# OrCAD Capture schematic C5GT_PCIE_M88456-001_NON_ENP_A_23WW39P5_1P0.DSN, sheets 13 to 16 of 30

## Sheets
13 DDR3B - x64 SMC: size B
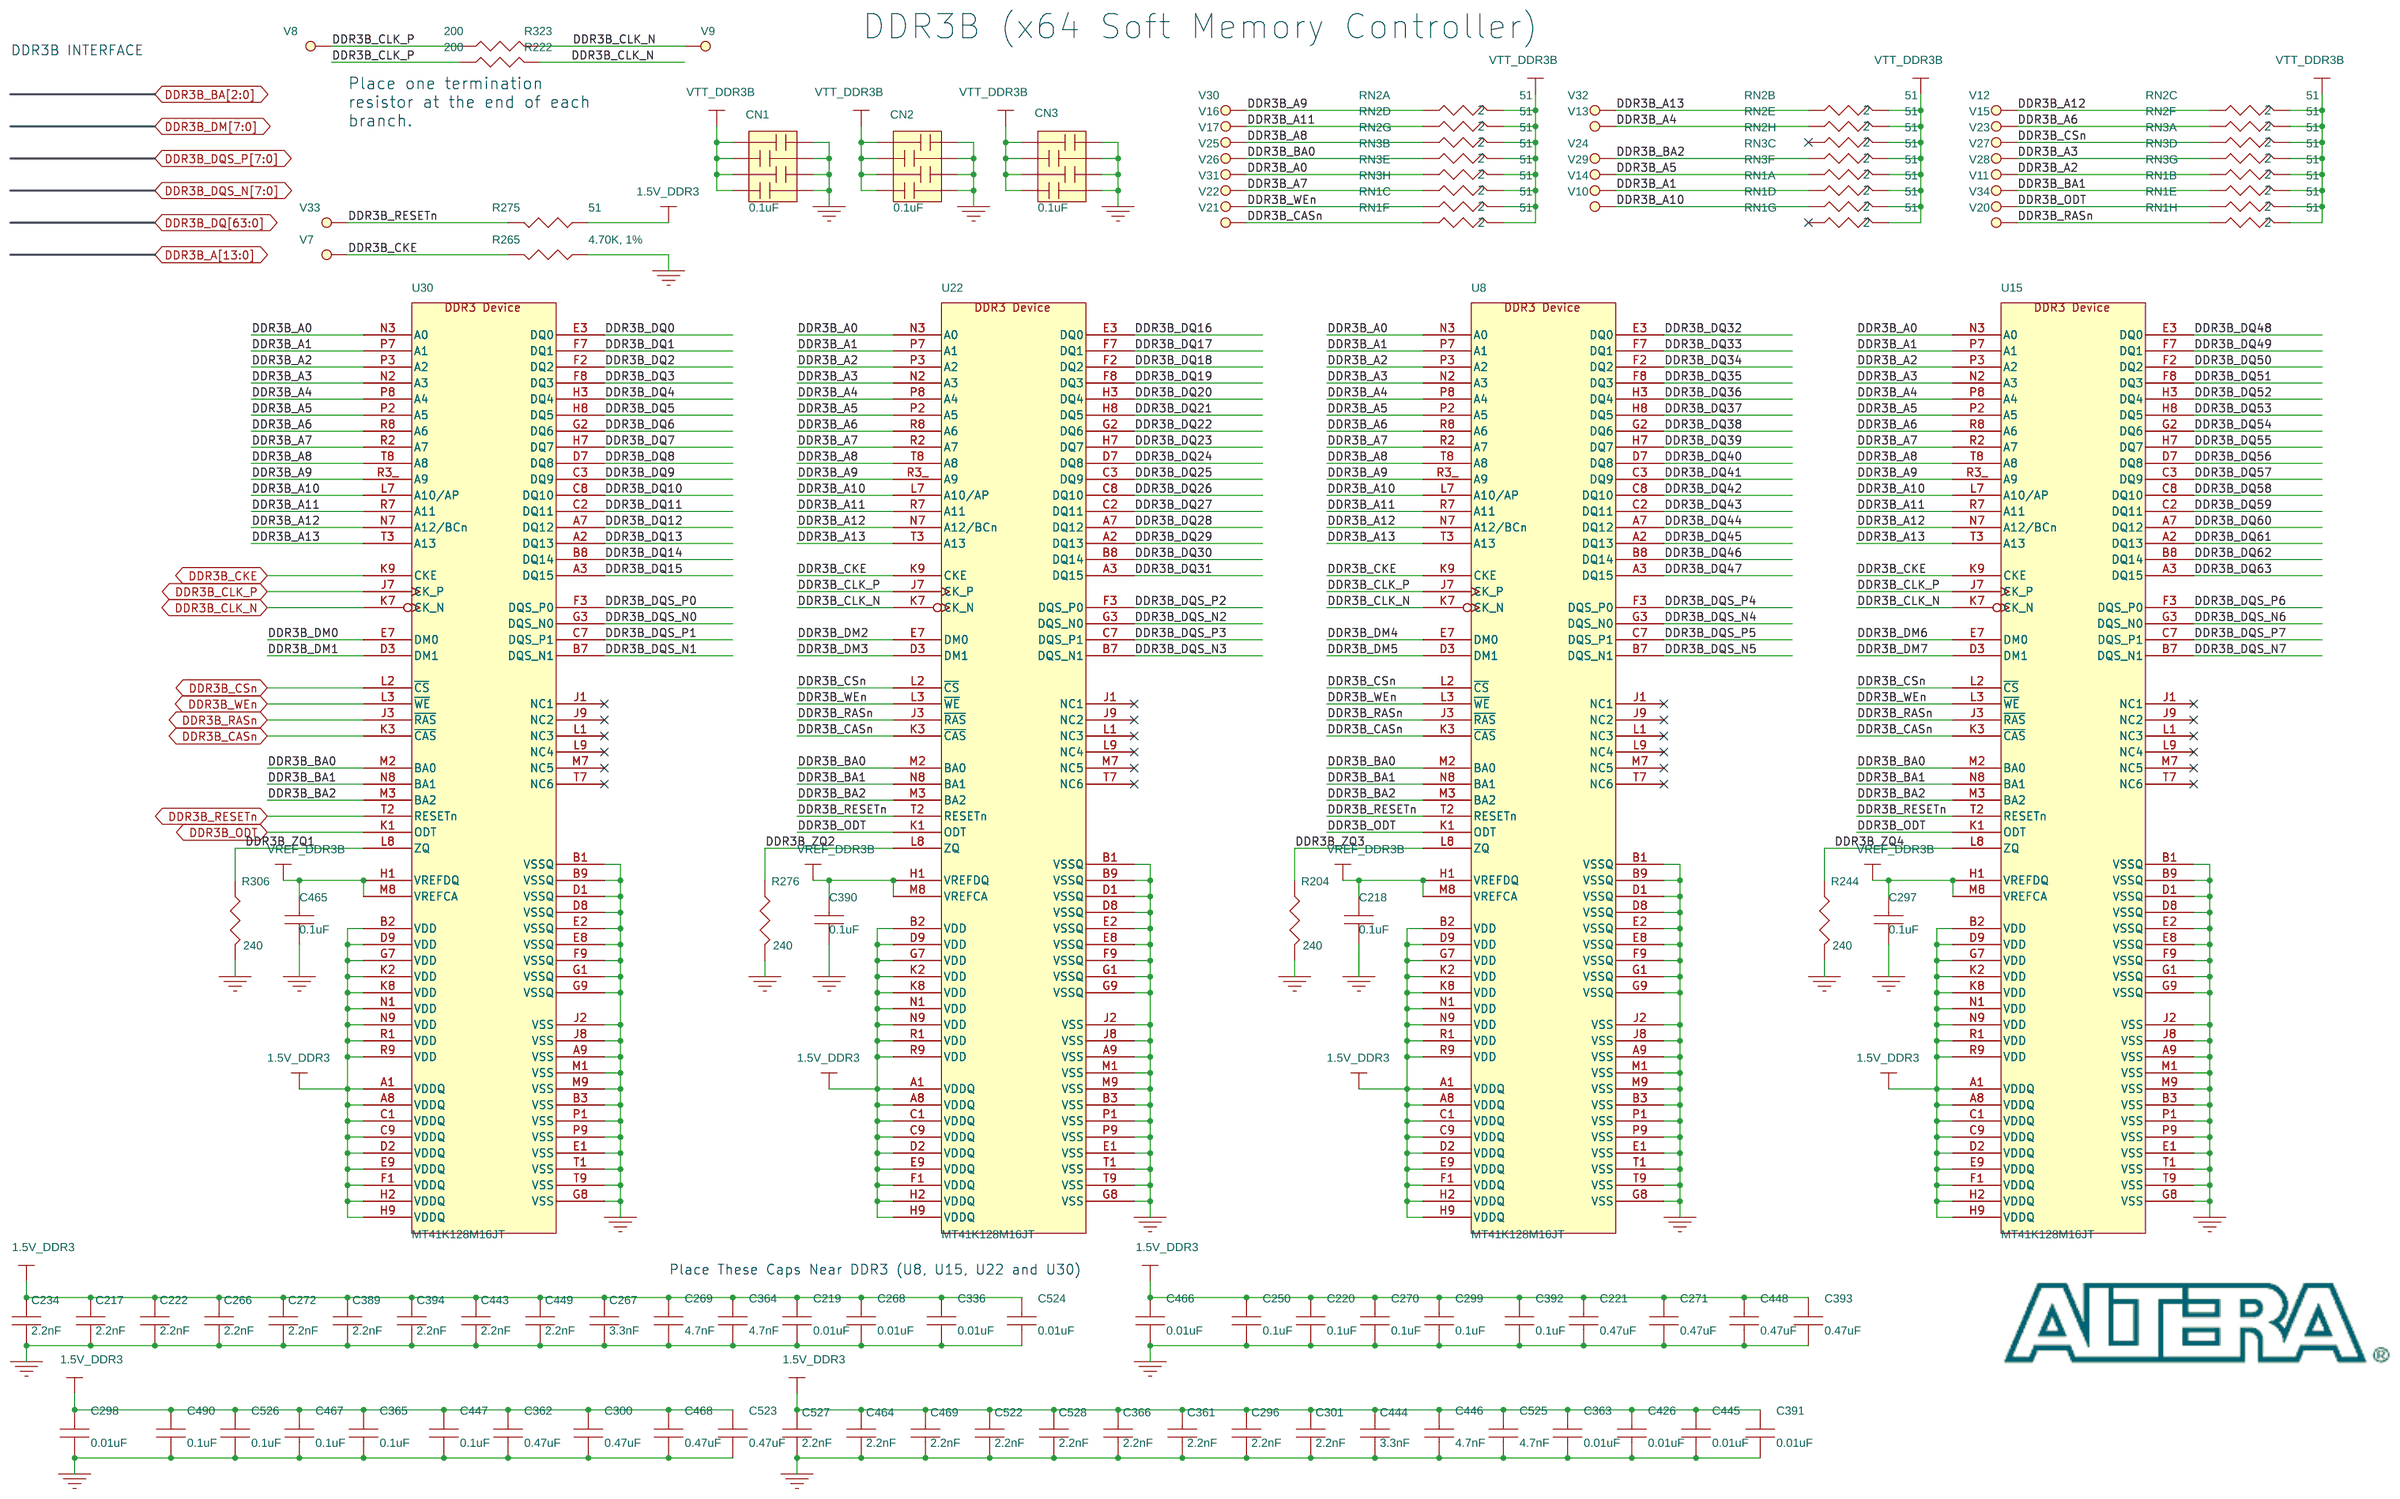
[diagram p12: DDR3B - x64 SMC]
14 Flash: size B
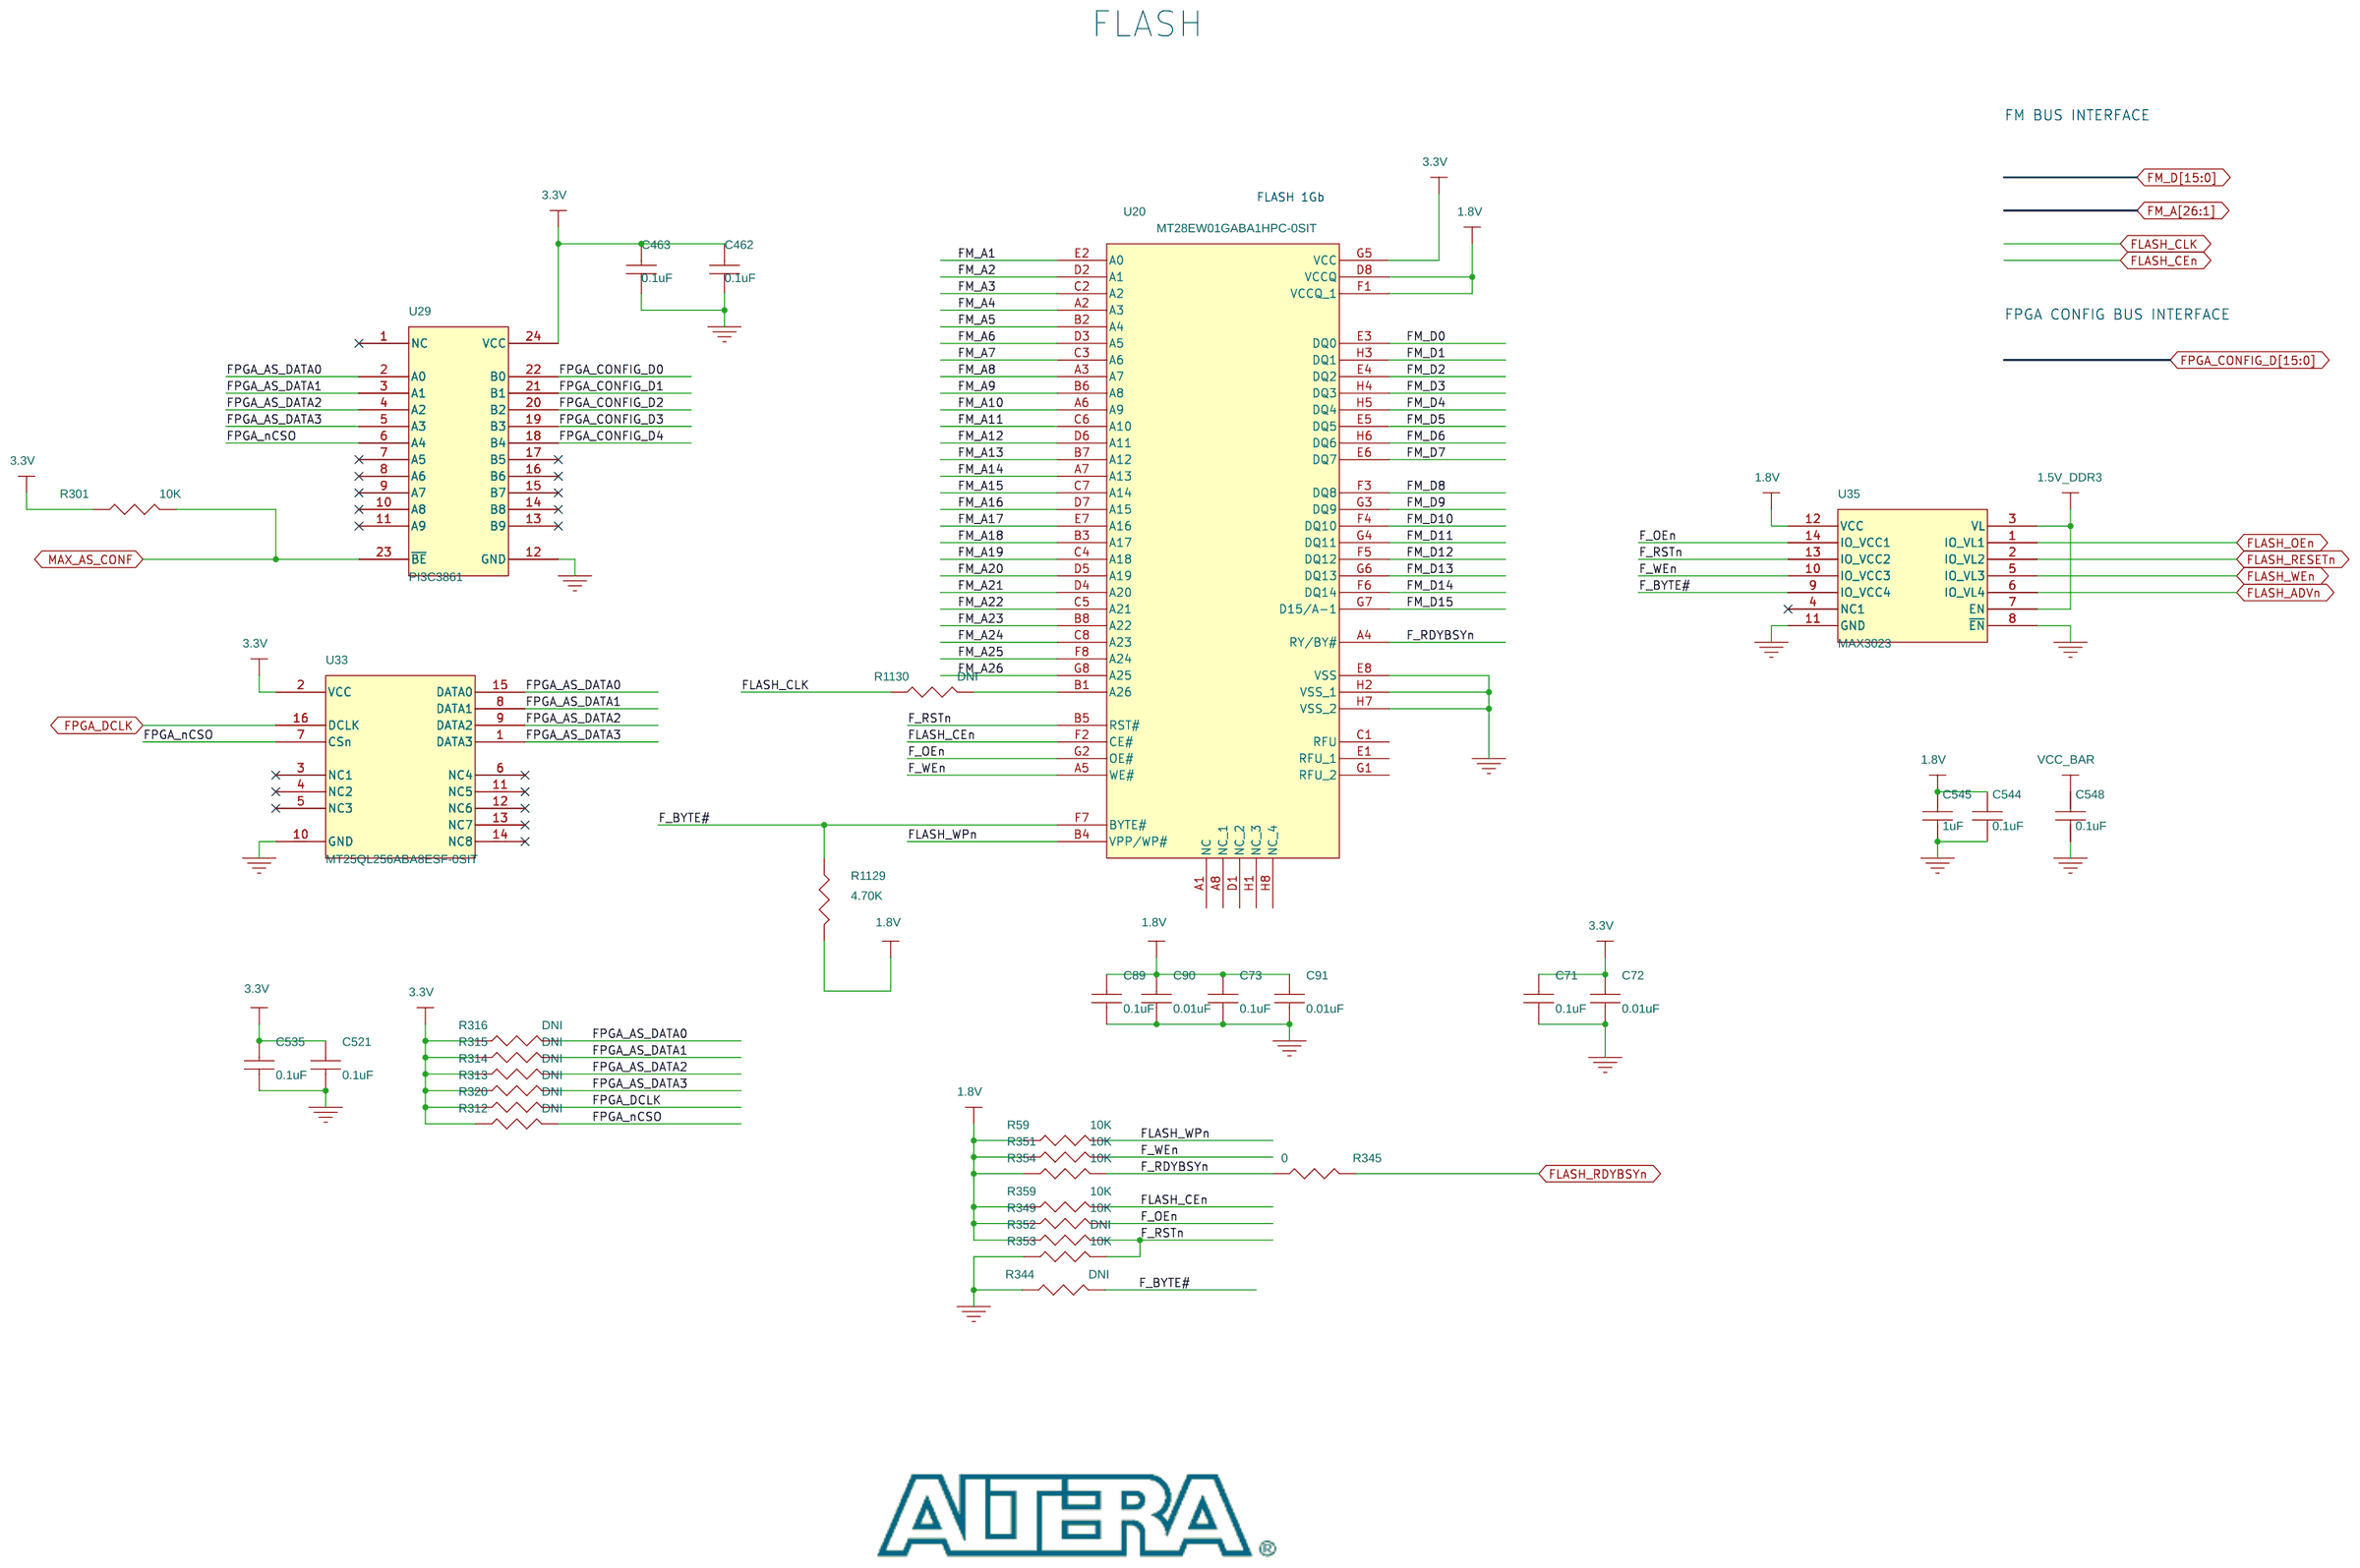
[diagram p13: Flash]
15 5M2210 System Controller: size B
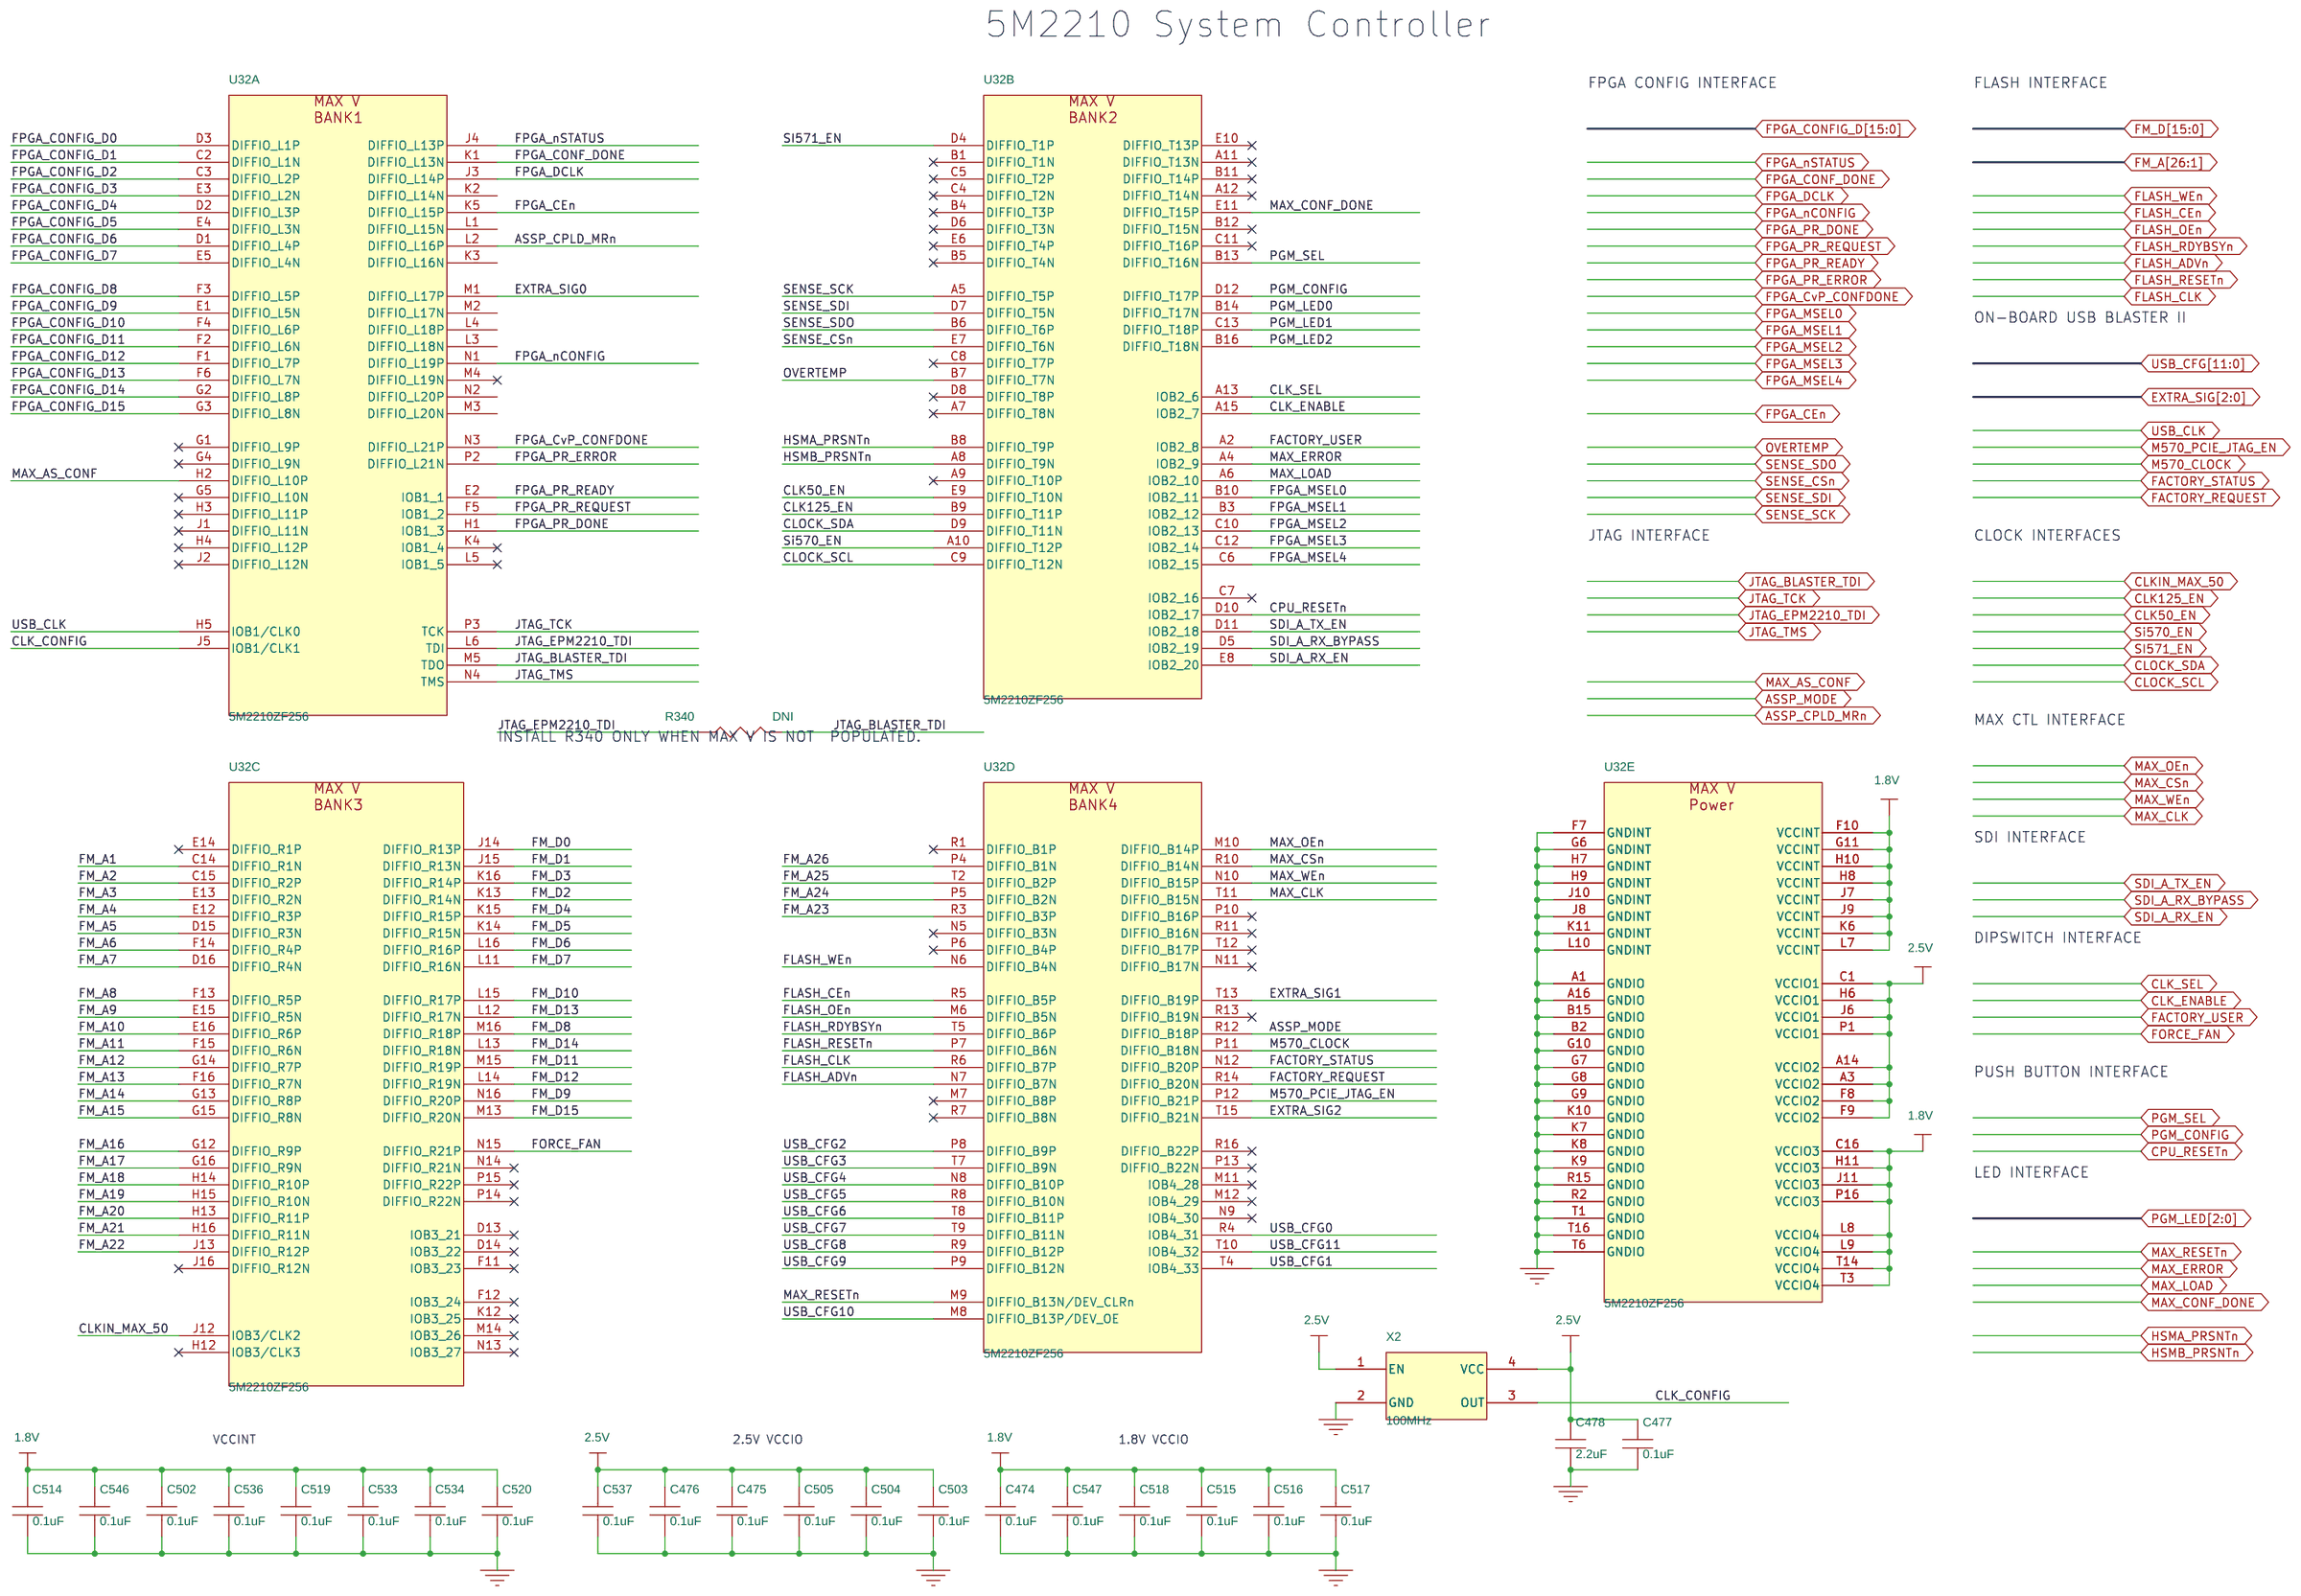
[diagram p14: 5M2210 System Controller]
16 SDI A Transmit/Receive: size B
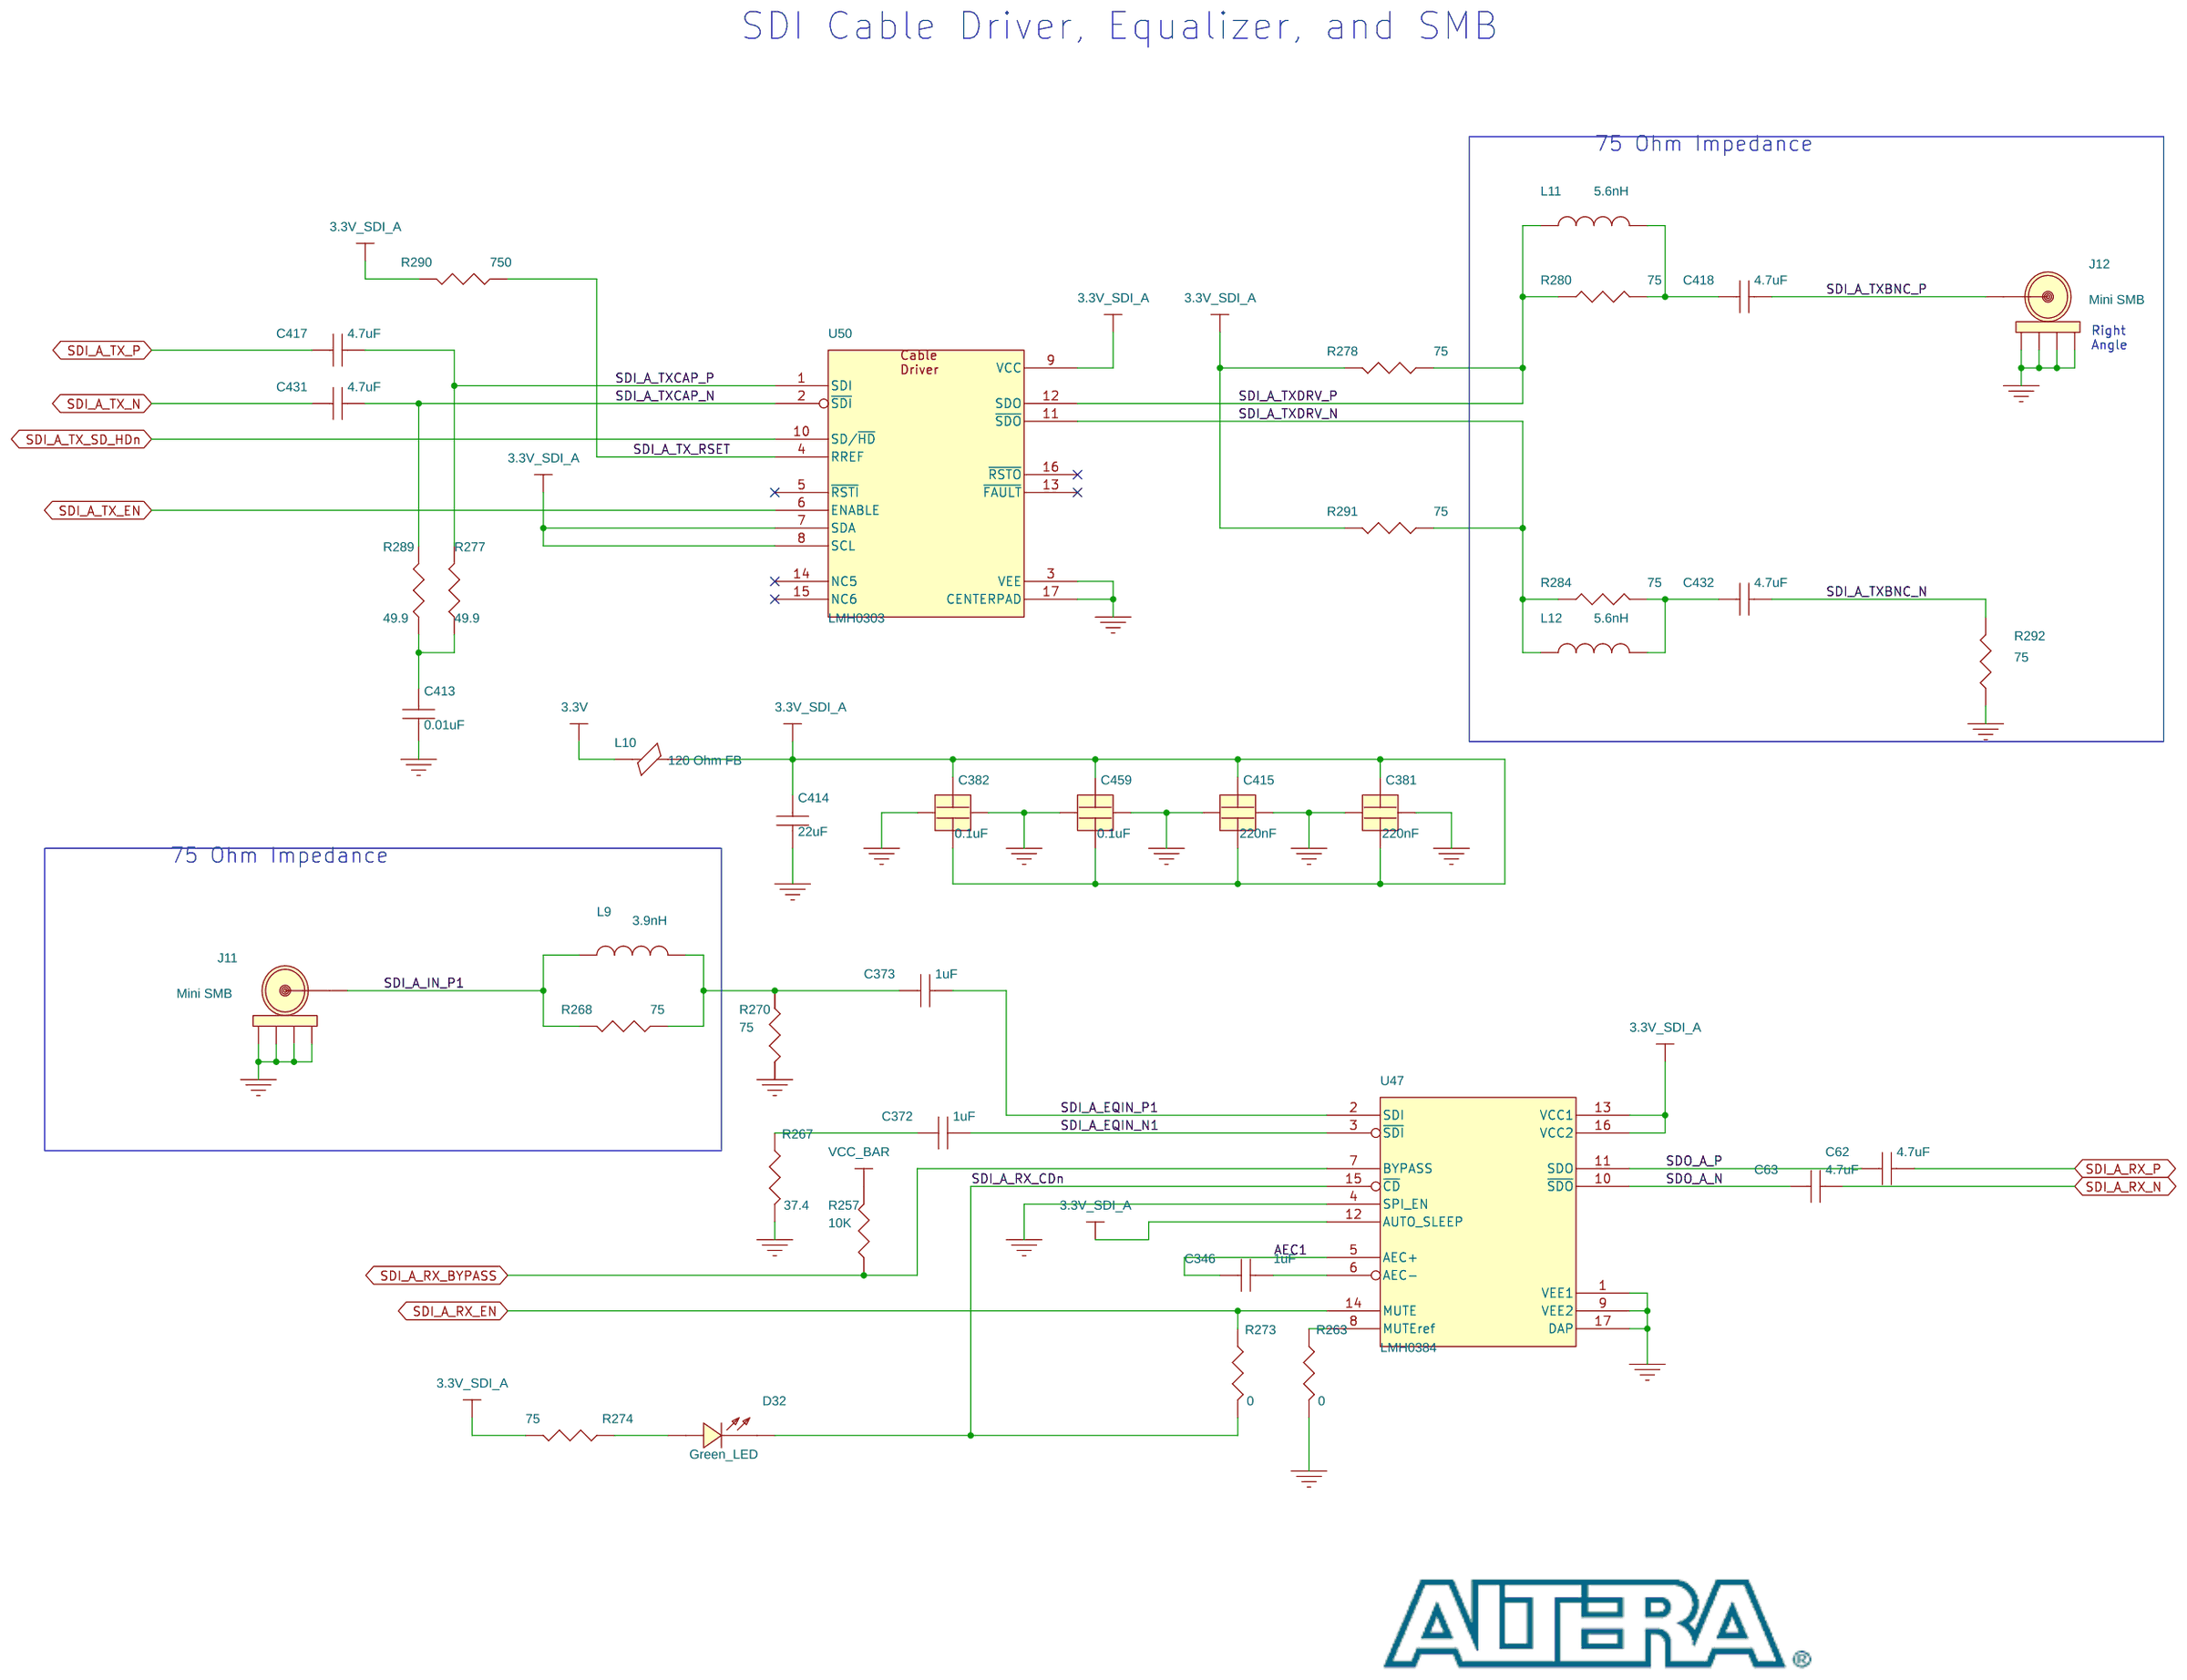
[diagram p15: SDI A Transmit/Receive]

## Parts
sheet 5M2210 System Controller
C474  0.1uF  [0402]
C475  0.1uF  [0402]
C476  0.1uF  [0402]
C477  0.1uF  [0402]
C478  2.2uF  [0603]
C502  0.1uF  [0402]
C503  0.1uF  [0402]
C504  0.1uF  [0402]
C505  0.1uF  [0402]
C514  0.1uF  [0402]
C515  0.1uF  [0402]
C516  0.1uF  [0402]
C517  0.1uF  [0402]
C518  0.1uF  [0402]
C519  0.1uF  [0402]
C520  0.1uF  [0402]
C533  0.1uF  [0402]
C534  0.1uF  [0402]
C536  0.1uF  [0402]
C537  0.1uF  [0402]
C546  0.1uF  [0402]
C547  0.1uF  [0402]
R340  DNI  [0402]
U32  5M2210ZF256  [F256]  (sections A,B,C,D,E)
X2  100MHz  [XTAL_XG-1000CB]
sheet DDR3B - x64 SMC
C217  2.2nF  [0402]
C218  0.1uF  [0402]
C219  0.01uF  [0402]
C220  0.1uF  [0402]
C221  0.47uF  [0402]
C222  2.2nF  [0402]
C234  2.2nF  [0402]
C250  0.1uF  [0402]
C266  2.2nF  [0402]
C267  3.3nF  [0402]
C268  0.01uF  [0402]
C269  4.7nF  [0402]
C270  0.1uF  [0402]
C271  0.47uF  [0402]
C272  2.2nF  [0402]
C296  2.2nF  [0402]
C297  0.1uF  [0402]
C298  0.01uF  [0402]
C299  0.1uF  [0402]
C300  0.47uF  [0402]
C301  2.2nF  [0402]
C336  0.01uF  [0402]
C361  2.2nF  [0402]
C362  0.47uF  [0402]
C363  0.01uF  [0402]
C364  4.7nF  [0402]
C365  0.1uF  [0402]
C366  2.2nF  [0402]
C389  2.2nF  [0402]
C390  0.1uF  [0402]
C391  0.01uF  [0402]
C392  0.1uF  [0402]
C393  0.47uF  [0402]
C394  2.2nF  [0402]
C426  0.01uF  [0402]
C443  2.2nF  [0402]
C444  3.3nF  [0402]
C445  0.01uF  [0402]
C446  4.7nF  [0402]
C447  0.1uF  [0402]
C448  0.47uF  [0402]
C449  2.2nF  [0402]
C464  2.2nF  [0402]
C465  0.1uF  [0402]
C466  0.01uF  [0402]
C467  0.1uF  [0402]
C468  0.47uF  [0402]
C469  2.2nF  [0402]
C490  0.1uF  [0402]
C522  2.2nF  [0402]
C523  0.47uF  [0402]
C524  0.01uF  [0402]
C525  4.7nF  [0402]
C526  0.1uF  [0402]
C527  2.2nF  [0402]
C528  2.2nF  [0402]
CN1  0.1uF  [CAP_PACK_4_1206]
CN2  0.1uF  [CAP_PACK_4_1206]
CN3  0.1uF  [CAP_PACK_4_1206]
R204  240  [0402]
R222  200  [0402]
R244  240  [0402]
R265  4.70K, 1%  [0402]
R275  51  [0402]
R276  240  [0402]
R306  240  [0402]
R323  200  [0402]
RN1  51  [RES_PACK_8]  (sections A,B,C,D,E,F,G,H)
RN2  51  [RES_PACK_8]  (sections A,B,C,D,E,F,G,H)
RN3  51  [RES_PACK_8]  (sections A,B,C,D,E,F,G,H)
U8  MT41K128M16JT  [Micron_ddr3_96_9x14]
U15  MT41K128M16JT  [Micron_ddr3_96_9x14]
U22  MT41K128M16JT  [Micron_ddr3_96_9x14]
U30  MT41K128M16JT  [Micron_ddr3_96_9x14]
V7  VIA_1  [STAR_VIA]
V8  VIA_1  [STAR_VIA]
V9  VIA_1  [STAR_VIA]
V10  VIA_1  [STAR_VIA]
V11  VIA_1  [STAR_VIA]
V12  VIA_1  [STAR_VIA]
V13  VIA_1  [STAR_VIA]
V14  VIA_1  [STAR_VIA]
V15  VIA_1  [STAR_VIA]
V16  VIA_1  [STAR_VIA]
V17  VIA_1  [STAR_VIA]
V20  VIA_1  [STAR_VIA]
V21  VIA_1  [STAR_VIA]
V22  VIA_1  [STAR_VIA]
V23  VIA_1  [STAR_VIA]
V24  VIA_1  [STAR_VIA]
V25  VIA_1  [STAR_VIA]
V26  VIA_1  [STAR_VIA]
V27  VIA_1  [STAR_VIA]
V28  VIA_1  [STAR_VIA]
V29  VIA_1  [STAR_VIA]
V30  VIA_1  [STAR_VIA]
V31  VIA_1  [STAR_VIA]
V32  VIA_1  [STAR_VIA]
V33  VIA_1  [STAR_VIA]
V34  VIA_1  [STAR_VIA]
sheet Flash
C71  0.1uF  [0402]
C72  0.01uF  [0402]
C73  0.1uF  [0402]
C89  0.1uF  [0402]
C90  0.01uF  [0402]
C91  0.01uF  [0402]
C462  0.1uF  [0402]
C463  0.1uF  [0402]
C521  0.1uF  [0402]
C535  0.1uF  [0402]
C544  0.1uF  [0402]
C545  1uF  [0402]
C548  0.1uF  [0402]
R59  10K  [0402]
R301  10K  [0402]
R312  DNI  [0402]
R313  DNI  [0402]
R314  DNI  [0402]
R315  DNI  [0402]
R316  DNI  [0402]
R320  DNI  [0402]
R344  DNI  [0402]
R345  0  [0402]
R349  10K  [0402]
R351  10K  [0402]
R352  DNI  [0402]
R353  10K  [0402]
R354  10K  [0402]
R359  10K  [0402]
R1129  4.70K  [0402]
R1130  DNI  [0402]
U20  MT28EW01GABA1HPC-0SIT  [hc_tk0_bga64]
U29  PI3C3861  [QSOP24P]
U33  MT25QL256ABA8ESF-0SIT  [so16_wide]
U35  MAX3023  [TSSOP14]
sheet SDI A Transmit/Receive
C62  4.7uF  [0402]
C63  4.7uF  [0402]
C346  1uF  [0603]
C372  1uF  [0603]
C373  1uF  [0603]
C381  220nF  [X2Y_1206]
C382  0.1uF  [X2Y_0603]
C413  0.01uF  [0402]
C414  22uF  [1210]
C415  220nF  [X2Y_1206]
C417  4.7uF  [0805]
C418  4.7uF  [0805]
C431  4.7uF  [0805]
C432  4.7uF  [0805]
C459  0.1uF  [X2Y_0603]
D32  Green_LED  [LUMEX_LED0805]
J11  Mini SMB  [SMB_RA_JACK_RECEP]
J12  Mini SMB  [SMB_RA_JACK_RECEP]
L9  3.9nH  [0402]
L10  120 Ohm FB  [0603]
L11  5.6nH  [0402]
L12  5.6nH  [0402]
R257  10K  [0402]
R263  0  [0402]
R267  37.4  [0402]
R268  75  [0402]
R270  75  [0402]
R273  0  [0402]
R274  75  [0402]
R277  49.9  [0402]
R278  75  [0402]
R280  75  [0402]
R284  75  [0402]
R289  49.9  [0402]
R290  750  [0603]
R291  75  [0402]
R292  75  [0402]
U47  LMH0384  [LLP16_EPAD]
U50  LMH0303  [LLP16_EPAD]

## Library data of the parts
C71 C73 C89 C220 C250 C270 C299 C365 C392 C447 C467 C474-C476 C490 C502-C505 C514-C521 C526 C533-C537 C544 C546-C548 = CAP: CAP - CERAMIC,  0.1UF 0402 25VDC Y5V; Dielectric: X5R; IPN: K13560-001; Item Num: P03-15057R; LIFECYCLE_PHASE: Active; Lead Free Status: Lead Free; Manufacturer: Murata; Manufacturer Part Num: GRM155F51E104ZA01D; Num Pins: 2; Part Class: CAPACITORS; Price: 0.07; RoHS Compliant: RoHS Compliant; Tolerance: +80%/-20%
C218 C390 C477 = CAP: CAP - CERAMIC,  0.1UF 0402 25VDC Y5V; AGILE_LINK: http://sj-agile9app/Agile/PLMServlet?action=OpenEmailObject&classid=10000&objid=213459527; IPN: K13560-001; Item Num: P03-15057R; LIFECYCLE_PHASE: Active; Lead Free Status: Lead Free; MFR_LIFECYCLE: Active; Manufacturer: Murata; Manufacturer Part Num: GRM155F51E104ZA01D; Num Pins: 2; PART_SUBCLASS: CAPACITORS; Part Class: CAPACITORS; RATED_VOLTAGE: 25V; RoHS Compliant: RoHS Compliant; TOLERANCE: +80%/-20%
C478 = CAP: CAP, CERAMIC, 2.2UF, 10%, 10VDC, X5R, 0603; AGILE_LINK: http://sj-agile9app/Agile/PLMServlet?action=OpenEmailObject&classid=10000&objid=256999866; IPN: M97320-001; Item Num: P03-15213R; LIFECYCLE_PHASE: Active; Lead Free Status: Lead Free; MFR_LIFECYCLE: Active; Manufacturer: Murata; Manufacturer Part Num: GRM188R61A225KE34x; Num Pins: 2; PART_SUBCLASS: CAPACITORS; RATED_VOLTAGE: 10V; RoHS Compliant: RoHS Compliant; Supplier Part Num: 490-1545-1-ND; TOLERANCE: +/-10%
R340 = RESISTOR: RES ZERO OHM 1/16W 5% 0402 SMD; Altera Part No.: P02-14020R; IPN: A93549-001; Item Num: P02-14020R; Lead Free Status: No; Manufacturer: Panasonic; Manufacturer Part Num: ERJ-2GE0R00X; Num Pins: 2; Part Class: RESISTORS; Price: 0; RoHS Compliant: Yes; Tolerance: 5%
U32 = 5M2210ZF256: IC - Max V CPLD, 2210 LEs, 256FBGA 1.8V VCCINT; IPN: 965739; Item Num: P01-17326R; LIFECYCLE_PHASE: Preliminary; Lead Free Status: Lead Free; MFR_LIFECYCLE: Active; Manufacturer: Altera Corporation; Manufacturer Part Num: 5M2210ZF256C4N; Num Pins: 256; PART_SUBCLASS: ICS; RoHS Compliant: RoHS Compliant
X2 = OSC_ALT_1: OSC - 100MHZ, +/-50PPM, 2.5V, CMOS CLOCK OSCILLATOR, SMD; AGILE_LINK: http://sj-agile9app/Agile/PLMServlet?action=OpenEmailObject&classid=10000&objid=261083657; IPN: E98724-001; Item Num: P13-26910R; LIFECYCLE_PHASE: Active; Lead Free Status: Lead Free; MFR_LIFECYCLE: Active; Manufacturer: ECS, Inc.; Manufacturer Part Num: ECS-3525-1000-B-TR; Num Pins: 4; PART_SUBCLASS: OSCILLATORS; RoHS Compliant: RoHS Compliant
C217 C222 C234 C266 C272 C296 C301 C361 C366 C389 C394 C443 C449 C464 C469 C522 C527 C528 = CAP: CAP CER 2200PF 50V 10% X7R 0402; AGILE_LINK: http://sj-agile9app/Agile/PLMServlet?action=OpenEmailObject&classid=10000&objid=204246494; CAPACITANCE: 2200pF; IPN: A36096-022; Item Num: P03-15048R; LIFECYCLE_PHASE: Active; Manufacturer: Murata; Manufacturer Part Num: GRM155R71H222KA01D; Num Pins: 2; PART_SUBCLASS: CAPACITORS; RATED_VOLTAGE: 50V; TOLERANCE: +/-10%
C219 C268 C298 C336 C363 C391 C426 C445 C466 C524 = CAP: CAP, CER .01UF 16V X7R 0402; IPN: A36096-007; Item Num: P03-15137R; Lead Free Status: No; Manufacturer: Murata; Manufacturer Part Num: GRM155R71C103KA01D; Manufacturer's Part No.: GRM155R71C103KA01D; Num Pins: 2; Part Class: CAPACITORS; Price: 0; RoHS Compliant: Yes
C221 C271 C300 C362 C393 C448 C468 C523 = CAP: CAP - CER, 0.47UF, -20% +80%, 10V, Y5V, 0402; AGILE_LINK: http://sj-agile9app/Agile/PLMServlet?action=OpenEmailObject&classid=10000&objid=256989651; IPN: H94452-001; Item Num: P03-15192R; LIFECYCLE_PHASE: Active; Lead Free Status: Lead Free; MFR_LIFECYCLE: Active; Manufacturer: Murata; Manufacturer Part Num: GRM155F51A474ZE01x; Num Pins: 2; PART_SUBCLASS: CAPACITORS; Part Class: CAPACITORS; RATED_VOLTAGE: 10V; RoHS Compliant: RoHS Compliant; Supplier Part Num: 490-3276-1-ND; Tolerance: +80%/-20%
C267 C444 = CAP: CAP, CERAMIC, 3300PF, 10%, 50V, X7R, 0402; AGILE_LINK: http://sj-agile9app/Agile/PLMServlet?action=OpenEmailObject&classid=10000&objid=257002141; IPN: K13754-001; Item Num: P03-15215R; LIFECYCLE_PHASE: Active; Lead Free Status: Lead Free; MFR_LIFECYCLE: Active; Manufacturer: Murata; Manufacturer Part Num: GRM155F51H332ZA01x; Num Pins: 2; PART_SUBCLASS: CAPACITORS; RATED_VOLTAGE: 50V; RoHS Compliant: RoHS Compliant; TOLERANCE: +/-10%
C269 C364 C446 C525 = CAP: CAP - CER 4700PF 50V 10% X7R 0402; AGILE_LINK: http://sj-agile9app/Agile/PLMServlet?action=OpenEmailObject&classid=10000&objid=215384813; IPN: A36096-066; Item Num: P03-15074R; LIFECYCLE_PHASE: Active; Lead Free Status: Lead Free; MFR_LIFECYCLE: Active; Manufacturer: Murata; Manufacturer Part Num: GRM155R71H472KA01D; Num Pins: 2; PACKAGING: Tape & Reel (TR); PART_SUBCLASS: CAPACITORS; RATED_VOLTAGE: 50V; RoHS Compliant: RoHS Compliant; Supplier Part Num: GRM155R71H472KA01D; Tolerance: +/-10%
C297 C465 = CAP: CAP - CERAMIC,  0.1UF 0402 25VDC Y5V; AGILE_LINK: http://sj-agile9app/Agile/PLMServlet?action=OpenEmailObject&classid=10000&objid=213459527; IPN: K13560-001; Item Num: P03-15057R; LIFECYCLE_PHASE: Active; Lead Free Status: Lead Free; MFR_LIFECYCLE: Active; Manufacturer: Murata; Manufacturer Part Num: GRM155F51E104ZA01D; Num Pins: 2; PART_SUBCLASS: CAPACITORS; Part Class: CAPACITORS; RATED_VOLTAGE: 25V; RoHS Compliant: RoHS Compliant
CN1-CN3 = CAP_ARRAY: CAPNET, 4 CAPS, CERAMIC, 0.1uF, 1206, 20%, 16VDC, X7R; IPN: M97316-001; Item Num: P03-11419R; Manufacturer: Panasonic; Manufacturer Part Num: ECJ-RVB1C104M
R204 R244 R276 R306 = RESISTOR: RES, 240 OHMS, 5%, 1/16W, 0402; AGILE_LINK: http://sj-agile9app/Agile/PLMServlet?action=OpenEmailObject&classid=10000&objid=258528063; IPN: K15734-001; Item Num: P02-15068R; LIFECYCLE_PHASE: Active; Lead Free Status: Lead Free; MFR_LIFECYCLE: Active; Manufacturer: Panasonic; Manufacturer Part Num: ERJ-2GEJ241x; Num Pins: 2; PART_SUBCLASS: RESISTORS; RoHS Compliant: RoHS Compliant
R222 R323 = RESISTOR: RES, 200 OHMS, 1.0%, 1/16W, 0402; IPN: A93548-060; Item Num: P02-10716R; Lead Free Status: No; Manufacturer: Panasonic; Manufacturer Part Num: ERJ-2RKF2000x; Num Pins: 2; Part Class: RESISTORS; Price: 0; RoHS Compliant: Yes; Tolerance: 1%
R265 = RESISTOR: RES,4.70K OHMS,1.0%,1/16W,0402; AGILE_LINK: http://sj-agile9app/Agile/PLMServlet?action=OpenEmailObject&classid=10000&objid=146753272; IPN: A93548-517; Item Num: P02-11384R; LIFECYCLE_PHASE: Active; MFR_LIFECYCLE: Active; Manufacturer: Vishay; Manufacturer Part Num: CRCW04024K70FKED; Num Pins: 2; PART_SUBCLASS: RESISTORS; POWER: 1/16W; RESISTANCE: 4.7K; TOLERANCE: +/-1%
R275 = RESISTOR: RES, 51 OHMS, 5%, 1/10W, 0402; IPN: K15861-001; Item Num: P02-16891R; Lead Free Status: Yes; Manufacturer: Panasonic; Manufacturer Part Num: ERJ-2GEJ510X; Num Pins: 2; Part Class: Resistors; Price: 0
RN1-RN3 = RES_PACK_0: RESNET - 51 OHM, 5%, 0.25W, 8-0402 RESISTORS,(3.8X1.6)MM, SMD; IPN: J41779-001; Item Num: P02-16648R; Lead Free Status: Yes; Manufacturer Part Num: EXB-2HV510JV; Manufacturer's Part No.: EXB-2HV510JV; Num Pins: 16; Part Class: RESISTORS; Price: 0; RoHS Compliant: Yes
U8 U15 U22 U30 = MT41J128M16HA: IC - DRAM, DDR3, 16MX16X8, 2Gb, CL11, ON-DIE-TERMINATION, 1.35/1.5V CORE/IO,533MHz. BGA-96, LEAD-FREE; IPN: K13937-001; Item Num: P01-17809R; Manufacturer: Micron; Manufacturer Part Num: MT41K128M16JT-125
V7-V17 V20-V34 = VIA_1: IPN: #N/A
C72 C90 C91 = CAP: CAP - CERAMIC,  0.1UF 0402 25VDC Y5V; CAPACITANCE: 0.1uF; Dielectric: X5R; IPN: K13560-001; Item Num: P03-15057R; LIFECYCLE_PHASE: Active; Lead Free Status: Lead Free; Manufacturer: Murata; Manufacturer Part Num: GRM155F51E104ZA01D; Num Pins: 2; Part Class: CAPACITORS; Price: 0.07; RoHS Compliant: RoHS Compliant; Tolerance: +80%/-20%
C462 C463 = CAP: CAP, CERAMIC CAP, 0.1UF, 10V, 10%, X5R, 0402; IPN: A36096-009; Item Num: P03-17013R; LIFECYCLE_PHASE: Active; Lead Free Status: Lead Free; Manufacturer: Murata; Manufacturer Part Num: GRM155R61A104KA01D; Num Pins: 2; Part Class: CAPACITORS; Price: 0; RoHS Compliant: RoHS Compliant
C545 = CAP: CAP - CER, 1UF, 10V, +/-10%, X5R, 0402; AGILE_LINK: http://sj-agile9app/Agile/PLMServlet?action=OpenEmailObject&classid=10000&objid=256999866; IPN: A36096-099; Item Num: P03-15479R; LIFECYCLE_PHASE: Active; Lead Free Status: Lead Free; MFR_LIFECYCLE: Active; Manufacturer: Murata; Manufacturer Part Num: GRM155R61A105KE15D; Num Pins: 2; PART_SUBCLASS: CAPACITORS; RATED_VOLTAGE: 10V; RoHS Compliant: RoHS Compliant; TOLERANCE: +/-10%
R59 R301 R312-R316 R320 R344 R349 R351-R354 R359 R1130 = RESISTOR: RES 10K OHM 1/16W 5% 0402 SMD; IPN: D83138-001; Item Num: P02-14023R; Lead Free Status: No; Manufacturer: Panasonic; Manufacturer Part Num: ERJ-2GEJ103X; Num Pins: 2; Part Class: RESISTORS; Price: 0; RoHS Compliant: Yes
R345 = RES_0_OHM_5%_1_16W_0402_SMD: IPN: A93549-001
R1129 = RESISTOR: RES,4.70K OHMS,1.0%,1/16W,0402; AGILE_LINK: http://sj-agile9app/Agile/PLMServlet?action=OpenEmailObject&classid=10000&objid=146753272; IPN: A93548-517; Item Num: P02-11384R; LIFECYCLE_PHASE: Active; Lead Free Status: No; MFR_LIFECYCLE: Active; Manufacturer: Vishay; Manufacturer Part Num: CRCW04024K70FKED; Num Pins: 2; PART_SUBCLASS: RESISTORS; POWER: 1/16W; RESISTANCE: 4.7K; RoHS Compliant: Yes; TOLERANCE: +/-1%
U20 = MT28EW01GABA1HPC-0SIT_3: IPN: K21740-001
U29 = IDTQS3861: IC - BUS SWITCH, 10-BIT, QSOP-24; IPN: N21403-001; Item Num: P01-13162R; Lead Free Status: No; Manufacturer: IDT; Manufacturer Part Num: PI3C3861-AQEX; Num Pins: 24; Part Class: ICs; Price: 0; RoHS Compliant: Yes
U33 = EPCQ256: IC - QUAD SERIAL CONFIGURATION (EPCQ), 256MB, (10.3X10.3)MM SOIC; IPN: J57561-001; Item Num: P01-17764R; Lead Free Status: Yes; Manufacturer: Altera Corporation; Num Pins: 8; Part Class: ICs
U35 = MAX3023: IC - QUAD LOW-VOLTAGE LEVEL TRANSLATOR, 100MBPS; IPN: K13968-001; Item Num: P01-17824R; Manufacturer: Maxim Integrated Products, Inc.; Manufacturer Part Num: MAX3023EUD+
C62 C63 = CAP: CAP - CERAMIC, 4.7UF, 6.3V, 10%, X5R, 0402; AGILE_LINK: http://sj-agile9app/Agile/PLMServlet?action=OpenEmailObject&classid=10000&objid=257560276; IPN: A36096-107; Item Num: P03-17432R; LIFECYCLE_PHASE: Active; Lead Free Status: Not Lead Free; MFR_LIFECYCLE: Active; Manufacturer: Murata; Manufacturer Part Num: GRM155R60J475ME87D; Num Pins: 2; PART_SUBCLASS: CAPACITORS; RATED_VOLTAGE: 6.3V; RoHS Compliant: RoHS Compliant; TOLERANCE: +/-10%
C346 C372 C373 = CAP: CAP - CERAMIC, 1.0UF, 10%, 6.3V, 0603, X5R; IPN: H86538-001; Item Num: P03-15095R; Lead Free Status: No; Manufacturer: Panasonic; Manufacturer Part Num: ECJ-1VB0J105K; Mfr Code: PAN; Num Pins: 2; Part Class: Capacitors; Price: 0; RoHS Compliant: Yes
C381 C415 = CAP_X2Y: CAP - X2Y, CER, 220NF, X7R 1206, 16V, +/-20%; AGILE_LINK: http://sj-agile9app/Agile/PLMServlet?action=OpenEmailObject&classid=10000&objid=257554660; IPN: K13603-001; Item Num: P03-15476R; LIFECYCLE_PHASE: Active; Lead Free Status: Not Lead Free; MFR_LIFECYCLE: Active; Manufacturer: Phycomp / Yageo; Manufacturer Part Num: CX1206MKX7R7BB224; Num Pins: 4; PART_SUBCLASS: CAPACITORS; RATED_VOLTAGE: 16V; RoHS Compliant: RoHS Compliant; TOLERANCE: +/-20%
C382 C459 = CAP_X2Y: CAP - X2Y, CER, 0.1UF, X7R 0603, 10V, +/-20%; AGILE_LINK: http://sj-agile9app/Agile/PLMServlet?action=OpenEmailObject&classid=10000&objid=257554634; IPN: K13756-001; Item Num: P03-15475R; LIFECYCLE_PHASE: Active; Lead Free Status: Not Lead Free; MFR_LIFECYCLE: Active; Manufacturer: Phycomp / Yageo; Manufacturer Part Num: CX0603MRX7R6BB104; Num Pins: 4; PART_SUBCLASS: CAPACITORS; RATED_VOLTAGE: 10V; RoHS Compliant: RoHS Compliant; TOLERANCE: +/-20%
C413 = CAP: CAP,CER,0.01UF,0402,10%,25VD; IPN: A36096-045; Item Num: P03-11343R; Lead Free Status: No; Manufacturer: Panasonic; Manufacturer Part Num: ECJ-0EB1E103K; Num Pins: 2; Part Class: Capacitors; Price: 0; RoHS Compliant: Yes
C414 = CAP: CAP - CERAMIC 22UF 10V X5R 10% 1210; AGILE_LINK: http://sj-agile9app/Agile/PLMServlet?action=OpenEmailObject&classid=10000&objid=216565517; IPN: K13608-001; Item Num: P03-15081R; LIFECYCLE_PHASE: Active; Lead Free Status: Lead Free; MFR_LIFECYCLE: Active; Manufacturer: Murata; Manufacturer Part Num: GRM32ER61A226KE20L; Num Pins: 2; PART_SUBCLASS: CAPACITORS; RATED_VOLTAGE: 10V; RoHS Compliant: RoHS Compliant; TOLERANCE: +/-10%
C417 C418 C431 C432 = CAP: CAP - CERAMIC, 4.7UF, 10%, 16V, 0805, X5R; IPN: M97318-001; Item Num: P03-15097R; Lead Free Status: No; Manufacturer: Panasonic; Manufacturer Part Num: ECJ-2FB1C475K; Mfr Code: PAN; Num Pins: 2; Part Class: Capacitors; Price: 0; RoHS Compliant: Yes; Supplier: xxxx; Supplier Part Num: xxxxx
D32 = LED: LED - GREEN, VF=2.0V, 0805 SMD; IPN: E63507-001; Item Num: P09-21120R; Lead Free Status: No; Manufacturer: Lumex, Inc.; Manufacturer Part Num: SML-LXT0805GW-TR; Num Pins: 2; Part Class: LEDs; RoHS Compliant: Yes
J11 J12 = CONN,_mini_SMB,_THM,_RA: IPN: K12133-001
L9 = INDUCTOR: IND - 3.9NH, 5%, 0402; AGILE_LINK: http://sj-agile9app/Agile/PLMServlet?action=OpenEmailObject&classid=10000&objid=259659196; IPN: K14429-001; Item Num: P04-16446R; LIFECYCLE_PHASE: Preliminary; Lead Free Status: Lead Free; MFR_LIFECYCLE: Active; Manufacturer: Coilcraft; Manufacturer Part Num: 0402CS-3N9XJLx; Num Pins: 2; PART_SUBCLASS: INDUCTORS; RoHS Compliant: RoHS Compliant
L10 = BEAD_FERRITE_SM: IND - EMIFIL FERRITE BEAD, 120 OHM, 25%, 0603; IPN: K14412-001; Item Num: P04-16045R; Lead Free Status: No; Manufacturer: Murata; Manufacturer Part Num: BLM18PG121SN1; Num Pins: 2; Part Class: Inductors; Price: 0; RoHS Compliant: Yes
L11 L12 = INDUCTOR: IND - 5.6NH 0402; AGILE_LINK: http://sj-agile9app/Agile/PLMServlet?action=OpenEmailObject&classid=10000&objid=215176093; IPN: M97349-001; Item Num: P04-16024R; LIFECYCLE_PHASE: Active; MFR_LIFECYCLE: Active; Manufacturer: Coilcraft; Manufacturer Part Num: 0402CS-5N6XJLW; Num Pins: 2; PACKAGING: Cut Tape (CT); PART_SUBCLASS: INDUCTORS; RoHS Compliant: RoHS Compliant; Supplier Part Num: 0402CS-5N6XJLU
R257 = RESISTOR: RES 10K OHM 1/16W 5% 0402 SMD; AGILE_LINK: http://sj-agile9app/Agile/PLMServlet?action=OpenEmailObject&classid=10000&objid=188481700; IPN: D83138-001; Item Num: P02-14023R; LIFECYCLE_PHASE: Active; MFR_LIFECYCLE: Active; Manufacturer: Panasonic; Manufacturer Part Num: ERJ-2GEJ103X; Num Pins: 2; PART_SUBCLASS: RESISTORS; POWER: 1/16W; RoHS Compliant: RoHS Compliant; TOLERANCE: +/-5%
R263 R273 = RESISTOR: RES ZERO OHM 1/16W 5% 0402 SMD; AGILE_LINK: http://sj-agile9app/Agile/PLMServlet?action=OpenEmailObject&classid=10000&objid=188481525; IPN: A93549-001; Item Num: P02-14020R; LIFECYCLE_PHASE: Active; MFR_LIFECYCLE: Active; Manufacturer: Panasonic; Manufacturer Part Num: ERJ-2GE0R00X; Num Pins: 2; PART_SUBCLASS: RESISTORS; POWER: 1/16W; RoHS Compliant: RoHS Compliant; TOLERANCE: +/-5%
R267 = RESISTOR: RES, 37.4 OHM, 1%, 1/16W, 0402; AGILE_LINK: http://sj-agile9app/Agile/PLMServlet?action=OpenEmailObject&classid=10000&objid=218075028; IPN: G41671-001; Item Num: P02-14099R; LIFECYCLE_PHASE: Active; MFR_LIFECYCLE: Active; Manufacturer: Panasonic; Manufacturer Part Num: ERJ-2RKF37R4X; Num Pins: 2; PART_SUBCLASS: RESISTORS; RoHS Compliant: RoHS Compliant
R268 R270 R274 R278 R280 R284 R291 R292 = RESISTOR: RES, 75 OHM, 5%, 1/16W, 0402; IPN: K15616-001; Item Num: P02-14103R; Lead Free Status: No; Manufacturer: Panasonic; Manufacturer Part Num: ERJ-2GEJ750X; Num Pins: 2; Part Class: Resistors; Price: 0
R277 R289 = RESISTOR: RES, 49.9 OHMS, 1%, 1/16W, 0402; IPN: K21587-001; Item Num: P02-14101R; Lead Free Status: Yes; Manufacturer: NIC Components Corp.; Manufacturer Part Num: NRC04F49R9TRF; Num Pins: 2; Part Class: Resistors; Price: 0
R290 = RESISTOR: RES, 750 OHMS, 5%, 1/10W, 0603; IPN: K15624-001; Item Num: P02-14118R; Lead Free Status: No; Manufacturer: Panasonic; Manufacturer Part Num: ERJ-3GEYJ751V; Num Pins: 2; Part Class: Resistors; Price: 0
U47 = LMH0384: IC - 3 Gbps HD/SD SDI Extended Reach and Configurable Adaptive Cable Equalizer, 16-LLP; AGILE_LINK: http://sj-agile9app/Agile/PLMServlet?action=OpenEmailObject&classid=10000&objid=258754816; IPN: K13939-001; Item Num: P01-17626R; LIFECYCLE_PHASE: Active; Lead Free Status: Lead Free; MFR_LIFECYCLE: Active; Manufacturer: National Semiconductor; Manufacturer Part Num: LMH0384SQ; Num Pins: 16; PART_SUBCLASS: ICS; RoHS Compliant: RoHS Compliant
U50 = LMH0303: IC - 3 Gbps HD/SD SDI Cable Driver with Cable Detect, 16-LLP; IPN: K13938-001; Item Num: P01-17627R; Lead Free Status: Yes; Manufacturer: National Semiconductor; Manufacturer Part Num: LMH0303SQx; Num Pins: 16; Part Class: ICs; Price: 0

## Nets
1.5V_DDR3: C217.1 C219.1 C220.1 C221.1 C222.1 C234.1 C250.1 C266.1 C267.1 C268.1 C269.1 C270.1 C271.1 C272.1 C296.1 C298.1 C299.1 C300.1 C301.1 C336.1 C361.1 C362.1 C363.1 C364.1 C365.1 C366.1 C389.1 C391.1 C392.1 C393.1 C394.1 C426.1 C443.1 C444.1 C445.1 C446.1 C447.1 C448.1 C449.1 C464.1 C466.1 C467.1 C468.1 C469.1 C490.1 C522.1 C523.1 C524.1 C525.1 C526.1 C527.1 C528.1 C548.1 R275.2 U8.A1(VDDQ) U8.A8(VDDQ) U8.B2(VDD) U8.C1(VDDQ) U8.C9(VDDQ) U8.D2(VDDQ) U8.D9(VDD) U8.E9(VDDQ) U8.F1(VDDQ) U8.G7(VDD) U8.H2(VDDQ) U8.H9(VDDQ) U8.K2(VDD) U8.K8(VDD) U8.N1(VDD) U8.N9(VDD) U8.R1(VDD) U8.R9(VDD) U15.A1(VDDQ) U15.A8(VDDQ) U15.B2(VDD) U15.C1(VDDQ) U15.C9(VDDQ) U15.D2(VDDQ) U15.D9(VDD) U15.E9(VDDQ) U15.F1(VDDQ) U15.G7(VDD) U15.H2(VDDQ) U15.H9(VDDQ) U15.K2(VDD) U15.K8(VDD) U15.N1(VDD) U15.N9(VDD) U15.R1(VDD) U15.R9(VDD) U22.A1(VDDQ) U22.A8(VDDQ) U22.B2(VDD) U22.C1(VDDQ) U22.C9(VDDQ) U22.D2(VDDQ) U22.D9(VDD) U22.E9(VDDQ) U22.F1(VDDQ) U22.G7(VDD) U22.H2(VDDQ) U22.H9(VDDQ) U22.K2(VDD) U22.K8(VDD) U22.N1(VDD) U22.N9(VDD) U22.R1(VDD) U22.R9(VDD) U30.A1(VDDQ) U30.A8(VDDQ) U30.B2(VDD) U30.C1(VDDQ) U30.C9(VDDQ) U30.D2(VDDQ) U30.D9(VDD) U30.E9(VDDQ) U30.F1(VDDQ) U30.G7(VDD) U30.H2(VDDQ) U30.H9(VDDQ) U30.K2(VDD) U30.K8(VDD) U30.N1(VDD) U30.N9(VDD) U30.R1(VDD) U30.R9(VDD) U35.3(VL) U35.7(EN) ; also on sheet 12 27 29
1.8V: C73.1 C89.1 C90.1 C91.1 C474.1 C502.1 C514.1 C515.1 C516.1 C517.1 C518.1 C519.1 C520.1 C533.1 C534.1 C536.1 C544.1 C545.1 C546.1 C547.1 R59.1 R349.1 R351.1 R352.1 R354.1 R359.1 R1129.1 U20.D8(VCCQ) U20.F1(VCCQ_1) U32.C16(VCCIO3) U32.F10(VCCINT) U32.G11(VCCINT) U32.H8(VCCINT) U32.H10(VCCINT) U32.H11(VCCIO3) U32.J7(VCCINT) U32.J9(VCCINT) U32.J11(VCCIO3) U32.K6(VCCINT) U32.L7(VCCINT) U32.L8(VCCIO4) U32.L9(VCCIO4) U32.P16(VCCIO3) U32.T3(VCCIO4) U32.T14(VCCIO4) U35.12(VCC) ; also on sheet 8 19 20 21 26 29
2.5V: C475.1 C476.1 C477.1 C478.1 C503.1 C504.1 C505.1 C537.1 U32.A3(VCCIO2) U32.A14(VCCIO2) U32.C1(VCCIO1) U32.F8(VCCIO2) U32.F9(VCCIO2) U32.H6(VCCIO1) U32.J6(VCCIO1) U32.P1(VCCIO1) X2.1(EN) X2.4(VCC) ; also on sheet 3 8 10 11 17 19 20 22 26 29
3.3V: C71.1 C72.1 C462.2 C463.2 C521.1 C535.1 L10.1 R301.1 R312.1 R313.1 R314.1 R315.1 R316.1 R320.1 U20.G5(VCC) U29.24(VCC) U33.2(VCC) ; also on sheet 8 18 19 20 21 23 24 25 26 27 28
3.3V_SDI_A: C381.A C381.B C382.A C382.B C414.1 C415.A C415.B C459.A C459.B L10.2 R257.2 R274.1 R278.2 R290.2 R291.2 U47.12(AUTO_SLEEP) U47.13(VCC1) U47.16(VCC2) U50.7(SDA) U50.8(SCL) U50.9(VCC)
GND: C71.2 C72.2 C73.2 C89.2 C90.2 C91.2 C217.2 C218.2 C219.2 C220.2 C221.2 C222.2 C234.2 C250.2 C266.2 C267.2 C268.2 C269.2 C270.2 C271.2 C272.2 C296.2 C297.2 C298.2 C299.2 C300.2 C301.2 C336.2 C361.2 C362.2 C363.2 C364.2 C365.2 C366.2 C381.G1 C381.G2 C382.G1 C382.G2 C389.2 C390.2 C391.2 C392.2 C393.2 C394.2 C413.2 C414.2 C415.G1 C415.G2 C426.2 C443.2 C444.2 C445.2 C446.2 C447.2 C448.2 C449.2 C459.G1 C459.G2 C462.1 C463.1 C464.2 C465.2 C466.2 C467.2 C468.2 C469.2 C474.2 C475.2 C476.2 C477.2 C478.2 C490.2 C502.2 C503.2 C504.2 C505.2 C514.2 C515.2 C516.2 C517.2 C518.2 C519.2 C520.2 C521.2 C522.2 C523.2 C524.2 C525.2 C526.2 C527.2 C528.2 C533.2 C534.2 C535.2 C536.2 C537.2 C544.2 C545.2 C546.2 C547.2 C548.2 CN1.5 CN1.6 CN1.7 CN1.8 CN2.5 CN2.6 CN2.7 CN2.8 CN3.5 CN3.6 CN3.7 CN3.8 J11.2 J11.3 J11.4 J11.5 J12.2 J12.3 J12.4 J12.5 R204.2 R244.2 R263.2 R265.2 R267.2 R270.2 R276.2 R292.1 R306.2 R344.1 R353.1 U8.A9(VSS) U8.B1(VSSQ) U8.B3(VSS) U8.B9(VSSQ) U8.D1(VSSQ) U8.D8(VSSQ) U8.E1(VSS) U8.E2(VSSQ) U8.E8(VSSQ) U8.F9(VSSQ) U8.G1(VSSQ) U8.G8(VSS) U8.G9(VSSQ) U8.J2(VSS) U8.J8(VSS) U8.M1(VSS) U8.M9(VSS) U8.P1(VSS) U8.P9(VSS) U8.T1(VSS) U8.T9(VSS) U15.A9(VSS) U15.B1(VSSQ) U15.B3(VSS) U15.B9(VSSQ) U15.D1(VSSQ) U15.D8(VSSQ) U15.E1(VSS) U15.E2(VSSQ) U15.E8(VSSQ) U15.F9(VSSQ) U15.G1(VSSQ) U15.G8(VSS) U15.G9(VSSQ) U15.J2(VSS) U15.J8(VSS) U15.M1(VSS) U15.M9(VSS) U15.P1(VSS) U15.P9(VSS) U15.T1(VSS) U15.T9(VSS) U20.E8(VSS) U20.H2(VSS_1) U20.H7(VSS_2) U22.A9(VSS) U22.B1(VSSQ) U22.B3(VSS) U22.B9(VSSQ) U22.D1(VSSQ) U22.D8(VSSQ) U22.E1(VSS) U22.E2(VSSQ) U22.E8(VSSQ) U22.F9(VSSQ) U22.G1(VSSQ) U22.G8(VSS) U22.G9(VSSQ) U22.J2(VSS) U22.J8(VSS) U22.M1(VSS) U22.M9(VSS) U22.P1(VSS) U22.P9(VSS) U22.T1(VSS) U22.T9(VSS) U29.12(GND) U30.A9(VSS) U30.B1(VSSQ) U30.B3(VSS) U30.B9(VSSQ) U30.D1(VSSQ) U30.D8(VSSQ) U30.E1(VSS) U30.E2(VSSQ) U30.E8(VSSQ) U30.F9(VSSQ) U30.G1(VSSQ) U30.G8(VSS) U30.G9(VSSQ) U30.J2(VSS) U30.J8(VSS) U30.M1(VSS) U30.M9(VSS) U30.P1(VSS) U30.P9(VSS) U30.T1(VSS) U30.T9(VSS) U32.A1(GNDIO) U32.A16(GNDIO) U32.B2(GNDIO) U32.B15(GNDIO) U32.F7(GNDINT) U32.G6(GNDINT) U32.G7(GNDIO) U32.G8(GNDIO) U32.G9(GNDIO) U32.G10(GNDIO) U32.H7(GNDINT) U32.H9(GNDINT) U32.J8(GNDINT) U32.J10(GNDINT) U32.K7(GNDIO) U32.K8(GNDIO) U32.K9(GNDIO) U32.K10(GNDIO) U32.K11(GNDINT) U32.L10(GNDINT) U32.R2(GNDIO) U32.R15(GNDIO) U32.T1(GNDIO) U32.T6(GNDIO) U32.T16(GNDIO) U33.10(GND) U35.8(~{EN}) U35.11(GND) U47.1(VEE1) U47.4(SPI_EN) U47.9(VEE2) U47.17(DAP) U50.3(VEE) U50.17(CENTERPAD) X2.2(GND) ; also on sheet 3 4 6 7 8 9 10 11 12 17 18 19 20 21 22 23 24 25 26 27 28 29 30
AEC1: C346.1 U47.5(AEC+)
ASSP_CPLD_MRn: U32.L2(DIFFIO_L16P) ; also on sheet 21
ASSP_MODE: U32.R12(DIFFIO_B18P) ; also on sheet 20
CLK50_EN: U32.E9(DIFFIO_T10N) ; also on sheet 8
CLK125_EN: U32.B9(DIFFIO_T11P) ; also on sheet 8
CLK_CONFIG: U32.J5(IOB1/CLK1) X2.3(OUT)
CLK_ENABLE: U32.A15(IOB2_7) ; also on sheet 20
CLK_SEL: U32.A13(IOB2_6) ; also on sheet 8 20
CLKIN_MAX_50: U32.J12(IOB3/CLK2) ; also on sheet 8
CLOCK_SCL: U32.C9(DIFFIO_T12N) ; also on sheet 8
CLOCK_SDA: U32.D9(DIFFIO_T11N) ; also on sheet 8
CPU_RESETn: U32.D10(IOB2_17) ; also on sheet 10 20
DDR3B_A0: RN3.5 U8.N3(A0) U15.N3(A0) U22.N3(A0) U30.N3(A0) V26.1(TP) ; also on sheet 5
DDR3B_A1: RN1.1 U8.P7(A1) U15.P7(A1) U22.P7(A1) U30.P7(A1) V14.1(TP) ; also on sheet 5
DDR3B_A2: RN3.7 U8.P3(A2) U15.P3(A2) U22.P3(A2) U30.P3(A2) V28.1(TP) ; also on sheet 5
DDR3B_A3: RN3.4 U8.N2(A3) U15.N2(A3) U22.N2(A3) U30.N2(A3) V27.1(TP) ; also on sheet 5
DDR3B_A4: RN2.5 U8.P8(A4) U15.P8(A4) U22.P8(A4) U30.P8(A4) V13.1(TP) ; also on sheet 5
DDR3B_A5: RN3.6 U8.P2(A5) U15.P2(A5) U22.P2(A5) U30.P2(A5) V29.1(TP) ; also on sheet 5
DDR3B_A6: RN2.6 U8.R8(A6) U15.R8(A6) U22.R8(A6) U30.R8(A6) V15.1(TP) ; also on sheet 5
DDR3B_A7: RN3.8 U8.R2(A7) U15.R2(A7) U22.R2(A7) U30.R2(A7) V31.1(TP) ; also on sheet 5
DDR3B_A8: RN2.7 U8.T8(A8) U15.T8(A8) U22.T8(A8) U30.T8(A8) V17.1(TP) ; also on sheet 5
DDR3B_A9: RN2.1 U8.R3 (A9) U15.R3 (A9) U22.R3 (A9) U30.R3 (A9) V30.1(TP) ; also on sheet 5
DDR3B_A10: RN1.4 U8.L7(A10/AP) U15.L7(A10/AP) U22.L7(A10/AP) U30.L7(A10/AP) V10.1(TP) ; also on sheet 5
DDR3B_A11: RN2.4 U8.R7(A11) U15.R7(A11) U22.R7(A11) U30.R7(A11) V16.1(TP) ; also on sheet 5
DDR3B_A12: RN2.3 U8.N7(A12/BCn) U15.N7(A12/BCn) U22.N7(A12/BCn) U30.N7(A12/BCn) V12.1(TP) ; also on sheet 9
DDR3B_A13: RN2.2 U8.T3(A13) U15.T3(A13) U22.T3(A13) U30.T3(A13) V32.1(TP) ; also on sheet 9
DDR3B_BA0: RN3.2 U8.M2(BA0) U15.M2(BA0) U22.M2(BA0) U30.M2(BA0) V25.1(TP) ; also on sheet 5
DDR3B_BA1: RN1.2 U8.N8(BA1) U15.N8(BA1) U22.N8(BA1) U30.N8(BA1) V11.1(TP) ; also on sheet 5
DDR3B_BA2: RN3.3 U8.M3(BA2) U15.M3(BA2) U22.M3(BA2) U30.M3(BA2) V24.1(TP) ; also on sheet 5
DDR3B_CASn: RN1.6 U8.K3(~{CAS}) U15.K3(~{CAS}) U22.K3(~{CAS}) U30.K3(~{CAS}) V21.1(TP) ; also on sheet 5
DDR3B_CKE: R265.1 U8.K9(CKE) U15.K9(CKE) U22.K9(CKE) U30.K9(CKE) V7.1(TP) ; also on sheet 5
DDR3B_CLK_N: R222.1 R323.1 U8.K7(CK_N) U15.K7(CK_N) U22.K7(CK_N) U30.K7(CK_N) V9.1(TP) ; also on sheet 5
DDR3B_CLK_P: R222.2 R323.2 U8.J7(CK_P) U15.J7(CK_P) U22.J7(CK_P) U30.J7(CK_P) V8.1(TP) ; also on sheet 5
DDR3B_CSn: RN3.1 U8.L2(~{CS}) U15.L2(~{CS}) U22.L2(~{CS}) U30.L2(~{CS}) V23.1(TP) ; also on sheet 9
DDR3B_DM0: U30.E7(DM0) ; also on sheet 5
DDR3B_DM1: U30.D3(DM1) ; also on sheet 5
DDR3B_DM2: U22.E7(DM0) ; also on sheet 5
DDR3B_DM3: U22.D3(DM1) ; also on sheet 9
DDR3B_DM4: U8.E7(DM0) ; also on sheet 5
DDR3B_DM5: U8.D3(DM1) ; also on sheet 5
DDR3B_DM6: U15.E7(DM0) ; also on sheet 5
DDR3B_DM7: U15.D3(DM1) ; also on sheet 5
DDR3B_DQ0: U30.E3(DQ0) ; also on sheet 5
DDR3B_DQ1: U30.F7(DQ1) ; also on sheet 5
DDR3B_DQ2: U30.F2(DQ2) ; also on sheet 5
DDR3B_DQ3: U30.F8(DQ3) ; also on sheet 5
DDR3B_DQ4: U30.H3(DQ4) ; also on sheet 5
DDR3B_DQ5: U30.H8(DQ5) ; also on sheet 5
DDR3B_DQ6: U30.G2(DQ6) ; also on sheet 5
DDR3B_DQ7: U30.H7(DQ7) ; also on sheet 5
DDR3B_DQ8: U30.D7(DQ8) ; also on sheet 5
DDR3B_DQ9: U30.C3(DQ9) ; also on sheet 5
DDR3B_DQ10: U30.C8(DQ10) ; also on sheet 5
DDR3B_DQ11: U30.C2(DQ11) ; also on sheet 5
DDR3B_DQ12: U30.A7(DQ12) ; also on sheet 5
DDR3B_DQ13: U30.A2(DQ13) ; also on sheet 5
DDR3B_DQ14: U30.B8(DQ14) ; also on sheet 5
DDR3B_DQ15: U30.A3(DQ15) ; also on sheet 5
DDR3B_DQ16: U22.E3(DQ0) ; also on sheet 5
DDR3B_DQ17: U22.F7(DQ1) ; also on sheet 5
DDR3B_DQ18: U22.F2(DQ2) ; also on sheet 5
DDR3B_DQ19: U22.F8(DQ3) ; also on sheet 5
DDR3B_DQ20: U22.H3(DQ4) ; also on sheet 9
DDR3B_DQ21: U22.H8(DQ5) ; also on sheet 5
DDR3B_DQ22: U22.G2(DQ6) ; also on sheet 5
DDR3B_DQ23: U22.H7(DQ7) ; also on sheet 5
DDR3B_DQ24: U22.D7(DQ8) ; also on sheet 5
DDR3B_DQ25: U22.C3(DQ9) ; also on sheet 5
DDR3B_DQ26: U22.C8(DQ10) ; also on sheet 5
DDR3B_DQ27: U22.C2(DQ11) ; also on sheet 5
DDR3B_DQ28: U22.A7(DQ12) ; also on sheet 5
DDR3B_DQ29: U22.A2(DQ13) ; also on sheet 5
DDR3B_DQ30: U22.B8(DQ14) ; also on sheet 5
DDR3B_DQ31: U22.A3(DQ15) ; also on sheet 5
DDR3B_DQ32: U8.E3(DQ0) ; also on sheet 5
DDR3B_DQ33: U8.F7(DQ1) ; also on sheet 5
DDR3B_DQ34: U8.F2(DQ2) ; also on sheet 5
DDR3B_DQ35: U8.F8(DQ3) ; also on sheet 5
DDR3B_DQ36: U8.H3(DQ4) ; also on sheet 5
DDR3B_DQ37: U8.H8(DQ5) ; also on sheet 5
DDR3B_DQ38: U8.G2(DQ6) ; also on sheet 5
DDR3B_DQ39: U8.H7(DQ7) ; also on sheet 5
DDR3B_DQ40: U8.D7(DQ8) ; also on sheet 5
DDR3B_DQ41: U8.C3(DQ9) ; also on sheet 5
DDR3B_DQ42: U8.C8(DQ10) ; also on sheet 5
DDR3B_DQ43: U8.C2(DQ11) ; also on sheet 5
DDR3B_DQ44: U8.A7(DQ12) ; also on sheet 5
DDR3B_DQ45: U8.A2(DQ13) ; also on sheet 5
DDR3B_DQ46: U8.B8(DQ14) ; also on sheet 5
DDR3B_DQ47: U8.A3(DQ15) ; also on sheet 5
DDR3B_DQ48: U15.E3(DQ0) ; also on sheet 5
DDR3B_DQ49: U15.F7(DQ1) ; also on sheet 5
DDR3B_DQ50: U15.F2(DQ2) ; also on sheet 5
DDR3B_DQ51: U15.F8(DQ3) ; also on sheet 5
DDR3B_DQ52: U15.H3(DQ4) ; also on sheet 5
DDR3B_DQ53: U15.H8(DQ5) ; also on sheet 5
DDR3B_DQ54: U15.G2(DQ6) ; also on sheet 5
DDR3B_DQ55: U15.H7(DQ7) ; also on sheet 5
DDR3B_DQ56: U15.D7(DQ8) ; also on sheet 5
DDR3B_DQ57: U15.C3(DQ9) ; also on sheet 5
DDR3B_DQ58: U15.C8(DQ10) ; also on sheet 5
DDR3B_DQ59: U15.C2(DQ11) ; also on sheet 5
DDR3B_DQ60: U15.A7(DQ12) ; also on sheet 5
DDR3B_DQ61: U15.A2(DQ13) ; also on sheet 5
DDR3B_DQ62: U15.B8(DQ14) ; also on sheet 5
DDR3B_DQ63: U15.A3(DQ15) ; also on sheet 5
DDR3B_DQS_N0: U30.G3(DQS_N0) ; also on sheet 5
DDR3B_DQS_N1: U30.B7(DQS_N1) ; also on sheet 5
DDR3B_DQS_N2: U22.G3(DQS_N0) ; also on sheet 5
DDR3B_DQS_N3: U22.B7(DQS_N1) ; also on sheet 5
DDR3B_DQS_N4: U8.G3(DQS_N0) ; also on sheet 5
DDR3B_DQS_N5: U8.B7(DQS_N1) ; also on sheet 5
DDR3B_DQS_N6: U15.G3(DQS_N0) ; also on sheet 5
DDR3B_DQS_N7: U15.B7(DQS_N1) ; also on sheet 5
DDR3B_DQS_P0: U30.F3(DQS_P0) ; also on sheet 5
DDR3B_DQS_P1: U30.C7(DQS_P1) ; also on sheet 5
DDR3B_DQS_P2: U22.F3(DQS_P0) ; also on sheet 5
DDR3B_DQS_P3: U22.C7(DQS_P1) ; also on sheet 5
DDR3B_DQS_P4: U8.F3(DQS_P0) ; also on sheet 5
DDR3B_DQS_P5: U8.C7(DQS_P1) ; also on sheet 5
DDR3B_DQS_P6: U15.F3(DQS_P0) ; also on sheet 5
DDR3B_DQS_P7: U15.C7(DQS_P1) ; also on sheet 5
DDR3B_ODT: RN1.5 U8.K1(ODT) U15.K1(ODT) U22.K1(ODT) U30.K1(ODT) V34.1(TP) ; also on sheet 5
DDR3B_RASn: RN1.8 U8.J3(~{RAS}) U15.J3(~{RAS}) U22.J3(~{RAS}) U30.J3(~{RAS}) V20.1(TP) ; also on sheet 5
DDR3B_RESETn: R275.1 U8.T2(RESETn) U15.T2(RESETn) U22.T2(RESETn) U30.T2(RESETn) V33.1(TP) ; also on sheet 5
DDR3B_WEn: RN1.3 U8.L3(~{WE}) U15.L3(~{WE}) U22.L3(~{WE}) U30.L3(~{WE}) V22.1(TP) ; also on sheet 5
DDR3B_ZQ1: R306.1 U30.L8(ZQ)
DDR3B_ZQ2: R276.1 U22.L8(ZQ)
DDR3B_ZQ3: R204.1 U8.L8(ZQ)
DDR3B_ZQ4: R244.1 U15.L8(ZQ)
EXTRA_SIG0: U32.M1(DIFFIO_L17P) ; also on sheet 19
EXTRA_SIG1: U32.T13(DIFFIO_B19P) ; also on sheet 19
EXTRA_SIG2: U32.T15(DIFFIO_B21N) ; also on sheet 19
F_BYTE#: R344.2 R1129.2 U20.F7(BYTE#) U35.9(IO_VCC4)
F_OEn: R349.2 U20.G2(OE#) U35.14(IO_VCC1)
F_RDYBSYn: R345.2 R354.2 U20.A4(RY/BY#)
F_RSTn: R352.2 R353.2 U20.B5(RST#) U35.13(IO_VCC2)
F_WEn: R351.2 U20.A5(WE#) U35.10(IO_VCC3)
FACTORY_REQUEST: U32.R14(DIFFIO_B20N) ; also on sheet 19
FACTORY_STATUS: U32.N12(DIFFIO_B20P) ; also on sheet 19
FACTORY_USER: U32.A2(IOB2_8) ; also on sheet 20
FLASH_ADVn: U32.N7(DIFFIO_B7N) U35.6(IO_VL4) ; also on sheet 5
FLASH_CEn: R359.2 U20.F2(CE#) U32.R5(DIFFIO_B5P) ; also on sheet 10
FLASH_CLK: R1130.1 U32.R6(DIFFIO_B7P) ; also on sheet 10
FLASH_OEn: U32.M6(DIFFIO_B5N) U35.1(IO_VL1) ; also on sheet 4
FLASH_RDYBSYn: R345.1 U32.T5(DIFFIO_B6P) ; also on sheet 9
FLASH_RESETn: U32.P7(DIFFIO_B6N) U35.2(IO_VL2) ; also on sheet 4
FLASH_WEn: U32.N6(DIFFIO_B4N) U35.5(IO_VL3) ; also on sheet 4
FLASH_WPn: R59.2 U20.B4(VPP/WP#)
FM_A1: U20.E2(A0) U32.C14(DIFFIO_R1N) ; also on sheet 5
FM_A2: U20.D2(A1) U32.C15(DIFFIO_R2P) ; also on sheet 10
FM_A3: U20.C2(A2) U32.E13(DIFFIO_R2N) ; also on sheet 5
FM_A4: U20.A2(A3) U32.E12(DIFFIO_R3P) ; also on sheet 5
FM_A5: U20.B2(A4) U32.D15(DIFFIO_R3N) ; also on sheet 5
FM_A6: U20.D3(A5) U32.F14(DIFFIO_R4P) ; also on sheet 5
FM_A7: U20.C3(A6) U32.D16(DIFFIO_R4N) ; also on sheet 5
FM_A8: U20.A3(A7) U32.F13(DIFFIO_R5P) ; also on sheet 5
FM_A9: U20.B6(A8) U32.E15(DIFFIO_R5N) ; also on sheet 5
FM_A10: U20.A6(A9) U32.E16(DIFFIO_R6P) ; also on sheet 5
FM_A11: U20.C6(A10) U32.F15(DIFFIO_R6N) ; also on sheet 5
FM_A12: U20.D6(A11) U32.G14(DIFFIO_R7P) ; also on sheet 5
FM_A13: U20.B7(A12) U32.F16(DIFFIO_R7N) ; also on sheet 5
FM_A14: U20.A7(A13) U32.G13(DIFFIO_R8P) ; also on sheet 5
FM_A15: U20.C7(A14) U32.G15(DIFFIO_R8N) ; also on sheet 5
FM_A16: U20.D7(A15) U32.G12(DIFFIO_R9P) ; also on sheet 5
FM_A17: U20.E7(A16) U32.G16(DIFFIO_R9N) ; also on sheet 5
FM_A18: U20.B3(A17) U32.H14(DIFFIO_R10P) ; also on sheet 5
FM_A19: U20.C4(A18) U32.H15(DIFFIO_R10N) ; also on sheet 5
FM_A20: U20.D5(A19) U32.H13(DIFFIO_R11P) ; also on sheet 5
FM_A21: U20.D4(A20) U32.H16(DIFFIO_R11N) ; also on sheet 5
FM_A22: U20.C5(A21) U32.J13(DIFFIO_R12P) ; also on sheet 5
FM_A23: U20.B8(A22) U32.R3(DIFFIO_B3P) ; also on sheet 5
FM_A24: U20.C8(A23) U32.P5(DIFFIO_B2N) ; also on sheet 5
FM_A25: U20.F8(A24) U32.T2(DIFFIO_B2P) ; also on sheet 5
FM_A26: U20.G8(A25) U32.P4(DIFFIO_B1N) ; also on sheet 5
FM_D0: U20.E3(DQ0) U32.J14(DIFFIO_R13P) ; also on sheet 5
FM_D1: U20.H3(DQ1) U32.J15(DIFFIO_R13N) ; also on sheet 5
FM_D2: U20.E4(DQ2) U32.K13(DIFFIO_R14N) ; also on sheet 5
FM_D3: U20.H4(DQ3) U32.K16(DIFFIO_R14P) ; also on sheet 5
FM_D4: U20.H5(DQ4) U32.K15(DIFFIO_R15P) ; also on sheet 5
FM_D5: U20.E5(DQ5) U32.K14(DIFFIO_R15N) ; also on sheet 5
FM_D6: U20.H6(DQ6) U32.L16(DIFFIO_R16P) ; also on sheet 5
FM_D7: U20.E6(DQ7) U32.L11(DIFFIO_R16N) ; also on sheet 5
FM_D8: U20.F3(DQ8) U32.M16(DIFFIO_R18P) ; also on sheet 5
FM_D9: U20.G3(DQ9) U32.N16(DIFFIO_R20P) ; also on sheet 5
FM_D10: U20.F4(DQ10) U32.L15(DIFFIO_R17P) ; also on sheet 5
FM_D11: U20.G4(DQ11) U32.M15(DIFFIO_R19P) ; also on sheet 5
FM_D12: U20.F5(DQ12) U32.L14(DIFFIO_R19N) ; also on sheet 5
FM_D13: U20.G6(DQ13) U32.L12(DIFFIO_R17N) ; also on sheet 10
FM_D14: U20.F6(DQ14) U32.L13(DIFFIO_R18N) ; also on sheet 5
FM_D15: U20.G7(D15/A-1) U32.M13(DIFFIO_R20N) ; also on sheet 10
FORCE_FAN: U32.N15(DIFFIO_R21P) ; also on sheet 10
FPGA_AS_DATA0: R316.2 U29.2(A0) U33.15(DATA0)
FPGA_AS_DATA1: R315.2 U29.3(A1) U33.8(DATA1)
FPGA_AS_DATA2: R314.2 U29.4(A2) U33.9(DATA2)
FPGA_AS_DATA3: R313.2 U29.5(A3) U33.1(DATA3)
FPGA_CEn: U32.K5(DIFFIO_L15P) ; also on sheet 10
FPGA_CONF_DONE: U32.K1(DIFFIO_L13N) ; also on sheet 10
FPGA_CONFIG_D0: U29.22(B0) U32.D3(DIFFIO_L1P) ; also on sheet 10
FPGA_CONFIG_D1: U29.21(B1) U32.C2(DIFFIO_L1N) ; also on sheet 10
FPGA_CONFIG_D2: U29.20(B2) U32.C3(DIFFIO_L2P) ; also on sheet 10
FPGA_CONFIG_D3: U29.19(B3) U32.E3(DIFFIO_L2N) ; also on sheet 10
FPGA_CONFIG_D4: U29.18(B4) U32.D2(DIFFIO_L3P) ; also on sheet 10
FPGA_CONFIG_D5: U32.E4(DIFFIO_L3N) ; also on sheet 10
FPGA_CONFIG_D6: U32.D1(DIFFIO_L4P) ; also on sheet 10
FPGA_CONFIG_D7: U32.E5(DIFFIO_L4N) ; also on sheet 10
FPGA_CONFIG_D8: U32.F3(DIFFIO_L5P) ; also on sheet 10
FPGA_CONFIG_D9: U32.E1(DIFFIO_L5N) ; also on sheet 10
FPGA_CONFIG_D10: U32.F4(DIFFIO_L6P) ; also on sheet 10
FPGA_CONFIG_D11: U32.F2(DIFFIO_L6N) ; also on sheet 10
FPGA_CONFIG_D12: U32.F1(DIFFIO_L7P) ; also on sheet 10
FPGA_CONFIG_D13: U32.F6(DIFFIO_L7N) ; also on sheet 10
FPGA_CONFIG_D14: U32.G2(DIFFIO_L8P) ; also on sheet 10
FPGA_CONFIG_D15: U32.G3(DIFFIO_L8N) ; also on sheet 10
FPGA_CvP_CONFDONE: U32.N3(DIFFIO_L21P) ; also on sheet 10
FPGA_DCLK: R320.2 U32.J3(DIFFIO_L14P) U33.16(DCLK) ; also on sheet 10
FPGA_MSEL0: U32.B10(IOB2_11) ; also on sheet 10
FPGA_MSEL1: U32.B3(IOB2_12) ; also on sheet 10
FPGA_MSEL2: U32.C10(IOB2_13) ; also on sheet 10
FPGA_MSEL3: U32.C12(IOB2_14) ; also on sheet 10
FPGA_MSEL4: U32.C6(IOB2_15) ; also on sheet 10
FPGA_nCONFIG: U32.N1(DIFFIO_L19P) ; also on sheet 10
FPGA_nCSO: R312.2 U29.6(A4) U33.7(CSn)
FPGA_nSTATUS: U32.J4(DIFFIO_L13P) ; also on sheet 10
FPGA_PR_DONE: U32.H1(IOB1_3) ; also on sheet 10
FPGA_PR_ERROR: U32.P2(DIFFIO_L21N) ; also on sheet 10
FPGA_PR_READY: U32.E2(IOB1_1) ; also on sheet 10
FPGA_PR_REQUEST: U32.F5(IOB1_2) ; also on sheet 10
HSMA_PRSNTn: U32.B8(DIFFIO_T9P) ; also on sheet 6 18 20
HSMB_PRSNTn: U32.A8(DIFFIO_T9N) ; also on sheet 6 18 20
JTAG_BLASTER_TDI: R340.2 U32.M5(TDO) ; also on sheet 11 19
JTAG_EPM2210_TDI: R340.1 U32.L6(TDI) ; also on sheet 11
JTAG_TCK: U32.P3(TCK) ; also on sheet 10 11 18 19
JTAG_TMS: U32.N4(TMS) ; also on sheet 10 11 19
M570_CLOCK: U32.P11(DIFFIO_B18N) ; also on sheet 19
M570_PCIE_JTAG_EN: U32.P12(DIFFIO_B21P) ; also on sheet 19
MAX_AS_CONF: R301.2 U29.23(~{BE}) U32.H2(DIFFIO_L10P)
MAX_CLK: U32.T11(DIFFIO_B15N) ; also on sheet 9
MAX_CONF_DONE: U32.E11(DIFFIO_T15P) ; also on sheet 20
MAX_CSn: U32.R10(DIFFIO_B14N) ; also on sheet 5
MAX_ERROR: U32.A4(IOB2_9) ; also on sheet 20
MAX_LOAD: U32.A6(IOB2_10) ; also on sheet 20
MAX_OEn: U32.M10(DIFFIO_B14P) ; also on sheet 5
MAX_RESETn: U32.M9(DIFFIO_B13N/DEV_CLRn) ; also on sheet 20
MAX_WEn: U32.N10(DIFFIO_B15P) ; also on sheet 5
OVERTEMP: U32.B7(DIFFIO_T7N) ; also on sheet 29
PGM_CONFIG: U32.D12(DIFFIO_T17P) ; also on sheet 20
PGM_LED0: U32.B14(DIFFIO_T17N) ; also on sheet 20
PGM_LED1: U32.C13(DIFFIO_T18P) ; also on sheet 20
PGM_LED2: U32.B16(DIFFIO_T18N) ; also on sheet 20
PGM_SEL: U32.B13(DIFFIO_T16N) ; also on sheet 20
SDI_A_EQIN_N1: C372.2 U47.3(~{SDI})
SDI_A_EQIN_P1: C373.2 U47.2(SDI)
SDI_A_IN_P1: J11.1 L9.1 R268.2
SDI_A_RX_BYPASS: R257.1 U32.D5(IOB2_19) U47.7(BYPASS) ; also on sheet 4
SDI_A_RX_CDn: D32.2(CATHODE) R273.2 U47.15(~{CD})
SDI_A_RX_EN: R273.1 U32.E8(IOB2_20) U47.14(MUTE) ; also on sheet 4
SDI_A_RX_N: C63.2 ; also on sheet 7
SDI_A_RX_P: C62.2 ; also on sheet 7
SDI_A_TX_EN: U32.D11(IOB2_18) U50.6(ENABLE) ; also on sheet 4
SDI_A_TX_N: C431.1 ; also on sheet 7
SDI_A_TX_P: C417.1 ; also on sheet 7
SDI_A_TX_RSET: R290.1 U50.4(RREF)
SDI_A_TX_SD_HDn: U50.10(SD/~{HD}) ; also on sheet 4
SDI_A_TXBNC_N: C432.2 R292.2
SDI_A_TXBNC_P: C418.2 J12.1
SDI_A_TXCAP_N: C431.2 R289.2 U50.2(~{SDI})
SDI_A_TXCAP_P: C417.2 R277.2 U50.1(SDI)
SDI_A_TXDRV_N: L12.1 R284.1 R291.1 U50.11(~{SDO})
SDI_A_TXDRV_P: L11.1 R278.1 R280.1 U50.12(SDO)
SDO_A_N: C63.1 U47.10(~{SDO})
SDO_A_P: C62.1 U47.11(SDO)
SENSE_CSn: U32.E7(DIFFIO_T6N) ; also on sheet 29
SENSE_SCK: U32.A5(DIFFIO_T5P) ; also on sheet 29
SENSE_SDI: U32.D7(DIFFIO_T5N) ; also on sheet 29
SENSE_SDO: U32.B6(DIFFIO_T6P) ; also on sheet 29
SI570_EN: U32.A10(DIFFIO_T12P) ; also on sheet 8
SI571_EN: U32.D4(DIFFIO_T1P) ; also on sheet 8
USB_CFG0: U32.R4(IOB4_31) ; also on sheet 19
USB_CFG1: U32.T4(IOB4_33) ; also on sheet 19
USB_CFG2: U32.P8(DIFFIO_B9P) ; also on sheet 19
USB_CFG3: U32.T7(DIFFIO_B9N) ; also on sheet 19
USB_CFG4: U32.N8(DIFFIO_B10P) ; also on sheet 19
USB_CFG5: U32.R8(DIFFIO_B10N) ; also on sheet 19
USB_CFG6: U32.T8(DIFFIO_B11P) ; also on sheet 19
USB_CFG7: U32.T9(DIFFIO_B11N) ; also on sheet 19
USB_CFG8: U32.R9(DIFFIO_B12P) ; also on sheet 19
USB_CFG9: U32.P9(DIFFIO_B12N) ; also on sheet 19
USB_CFG10: U32.M8(DIFFIO_B13P/DEV_OE) ; also on sheet 19
USB_CFG11: U32.T10(IOB4_32) ; also on sheet 19
USB_CLK: U32.H5(IOB1/CLK0) ; also on sheet 9 19
VREF_DDR3B: C218.1 C297.1 C390.1 C465.1 U8.H1(VREFDQ) U8.M8(VREFCA) U15.H1(VREFDQ) U15.M8(VREFCA) U22.H1(VREFDQ) U22.M8(VREFCA) U30.H1(VREFDQ) U30.M8(VREFCA) ; also on sheet 22 27 30
VTT_DDR3B: CN1.1 CN1.2 CN1.3 CN1.4 CN2.1 CN2.2 CN2.3 CN2.4 CN3.1 CN3.2 CN3.3 CN3.4 RN1.9(2) RN1.10(2) RN1.11(2) RN1.12(2) RN1.13(2) RN1.14(2) RN1.15(2) RN1.16(2) RN2.9(2) RN2.10(2) RN2.11(2) RN2.12(2) RN2.13(2) RN2.14(2) RN2.15(2) RN2.16(2) RN3.9(2) RN3.10(2) RN3.11(2) RN3.12(2) RN3.13(2) RN3.14(2) RN3.15(2) RN3.16(2) ; also on sheet 27
N16524308: C418.1 L11.2 R280.2
N16524437: C432.1 L12.2 R284.2
N53852218: C373.1 L9.2 R268.1 R270.1
N53852234: C372.1 R267.1
N53852248: C346.2 U47.6(AEC-)
N53852282: R263.1 U47.8(MUTEref)
N53852310: D32.1(ANODE) R274.2
N110834200: C413.1 R277.1 R289.1
N128681259: R1130.2 U20.B1(A26)

Not connected (* = marked no-connect by the designer): RN1 7*; RN2 8*; U8 J1(NC1)* J9(NC2)* L1(NC3)* L9(NC4)* M7(NC5)* T7(NC6)*; U15 J1(NC1)* J9(NC2)* L1(NC3)* L9(NC4)* M7(NC5)* T7(NC6)*; U20 A1(NC) A8(NC_1) C1(RFU) D1(NC_2) E1(RFU_1) G1(RFU_2) H1(NC_3) H8(NC_4); U22 J1(NC1)* J9(NC2)* L1(NC3)* L9(NC4)* M7(NC5)* T7(NC6)*; U29 1(NC)* 7(A5)* 8(A6)* 9(A7)* 10(A8)* 11(A9)* 13(B9)* 14(B8)* 15(B7)* 16(B6)* 17(B5)*; U30 J1(NC1)* J9(NC2)* L1(NC3)* L9(NC4)* M7(NC5)* T7(NC6)*; U32 A7(DIFFIO_T8N)* A9(DIFFIO_T10P)* A11(DIFFIO_T13N)* A12(DIFFIO_T14N)* B1(DIFFIO_T1N)* B4(DIFFIO_T3P)* B5(DIFFIO_T4N)* B11(DIFFIO_T14P)* B12(DIFFIO_T15N)* C4(DIFFIO_T2N)* C5(DIFFIO_T2P)* C7(IOB2_16)* C8(DIFFIO_T7P)* C11(DIFFIO_T16P)* D6(DIFFIO_T3N)* D8(DIFFIO_T8P)* D13(IOB3_21)* D14(IOB3_22)* E6(DIFFIO_T4P)* E10(DIFFIO_T13P)* E14(DIFFIO_R1P)* F11(IOB3_23)* F12(IOB3_24)* G1(DIFFIO_L9P)* G4(DIFFIO_L9N)* G5(DIFFIO_L10N)* H3(DIFFIO_L11P)* H4(DIFFIO_L12P)* H12(IOB3/CLK3)* J1(DIFFIO_L11N)* J2(DIFFIO_L12N)* J16(DIFFIO_R12N)* K2(DIFFIO_L14N) K3(DIFFIO_L16N) K4(IOB1_4)* K12(IOB3_25)* L1(DIFFIO_L15N) L3(DIFFIO_L18N) L4(DIFFIO_L18P) L5(IOB1_5)* M2(DIFFIO_L17N) M3(DIFFIO_L20N) M4(DIFFIO_L19N)* M7(DIFFIO_B8P)* M11(IOB4_28)* M12(IOB4_29)* M14(IOB3_26)* N2(DIFFIO_L20P) N5(DIFFIO_B3N)* N9(IOB4_30)* N11(DIFFIO_B17N)* N13(IOB3_27)* N14(DIFFIO_R21N)* P6(DIFFIO_B4P)* P10(DIFFIO_B16P)* P13(DIFFIO_B22N)* P14(DIFFIO_R22N)* P15(DIFFIO_R22P)* R1(DIFFIO_B1P)* R7(DIFFIO_B8N)* R11(DIFFIO_B16N)* R13(DIFFIO_B19N)* R16(DIFFIO_B22P)* T12(DIFFIO_B17P)*; U33 3(NC1)* 4(NC2)* 5(NC3)* 6(NC4)* 11(NC5)* 12(NC6)* 13(NC7)* 14(NC8)*; U35 4(NC1)*; U50 5(~{RSTI})* 13(~{FAULT})* 14(NC5)* 15(NC6)* 16(~{RSTO})*

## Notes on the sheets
sheet 13
- DDR3B (x64 Soft Memory Controller)
- DDR3B INTERFACE
- Place one termination
  resistor at the end of each
  branch.
- Place These Caps Near DDR3 (U8, U15, U22 and U30)
sheet 14
- FLASH
- FM BUS INTERFACE
- FLASH 1Gb
- FPGA CONFIG BUS INTERFACE
sheet 15
- 5M2210 System Controller
- FPGA CONFIG INTERFACE
- FLASH INTERFACE
- ON-BOARD USB BLASTER II
- JTAG INTERFACE
- CLOCK INTERFACES
- INSTALL R340 ONLY WHEN MAX V IS NOT  POPULATED.
- MAX CTL INTERFACE
- SDI INTERFACE
- DIPSWITCH INTERFACE
- PUSH BUTTON INTERFACE
- LED INTERFACE
- VCCINT
- 2.5V VCCIO
- 1.8V VCCIO
sheet 16
- SDI Cable Driver, Equalizer, and SMB
- 75 Ohm Impedance
- Right
  Angle
- 75 Ohm Impedance
